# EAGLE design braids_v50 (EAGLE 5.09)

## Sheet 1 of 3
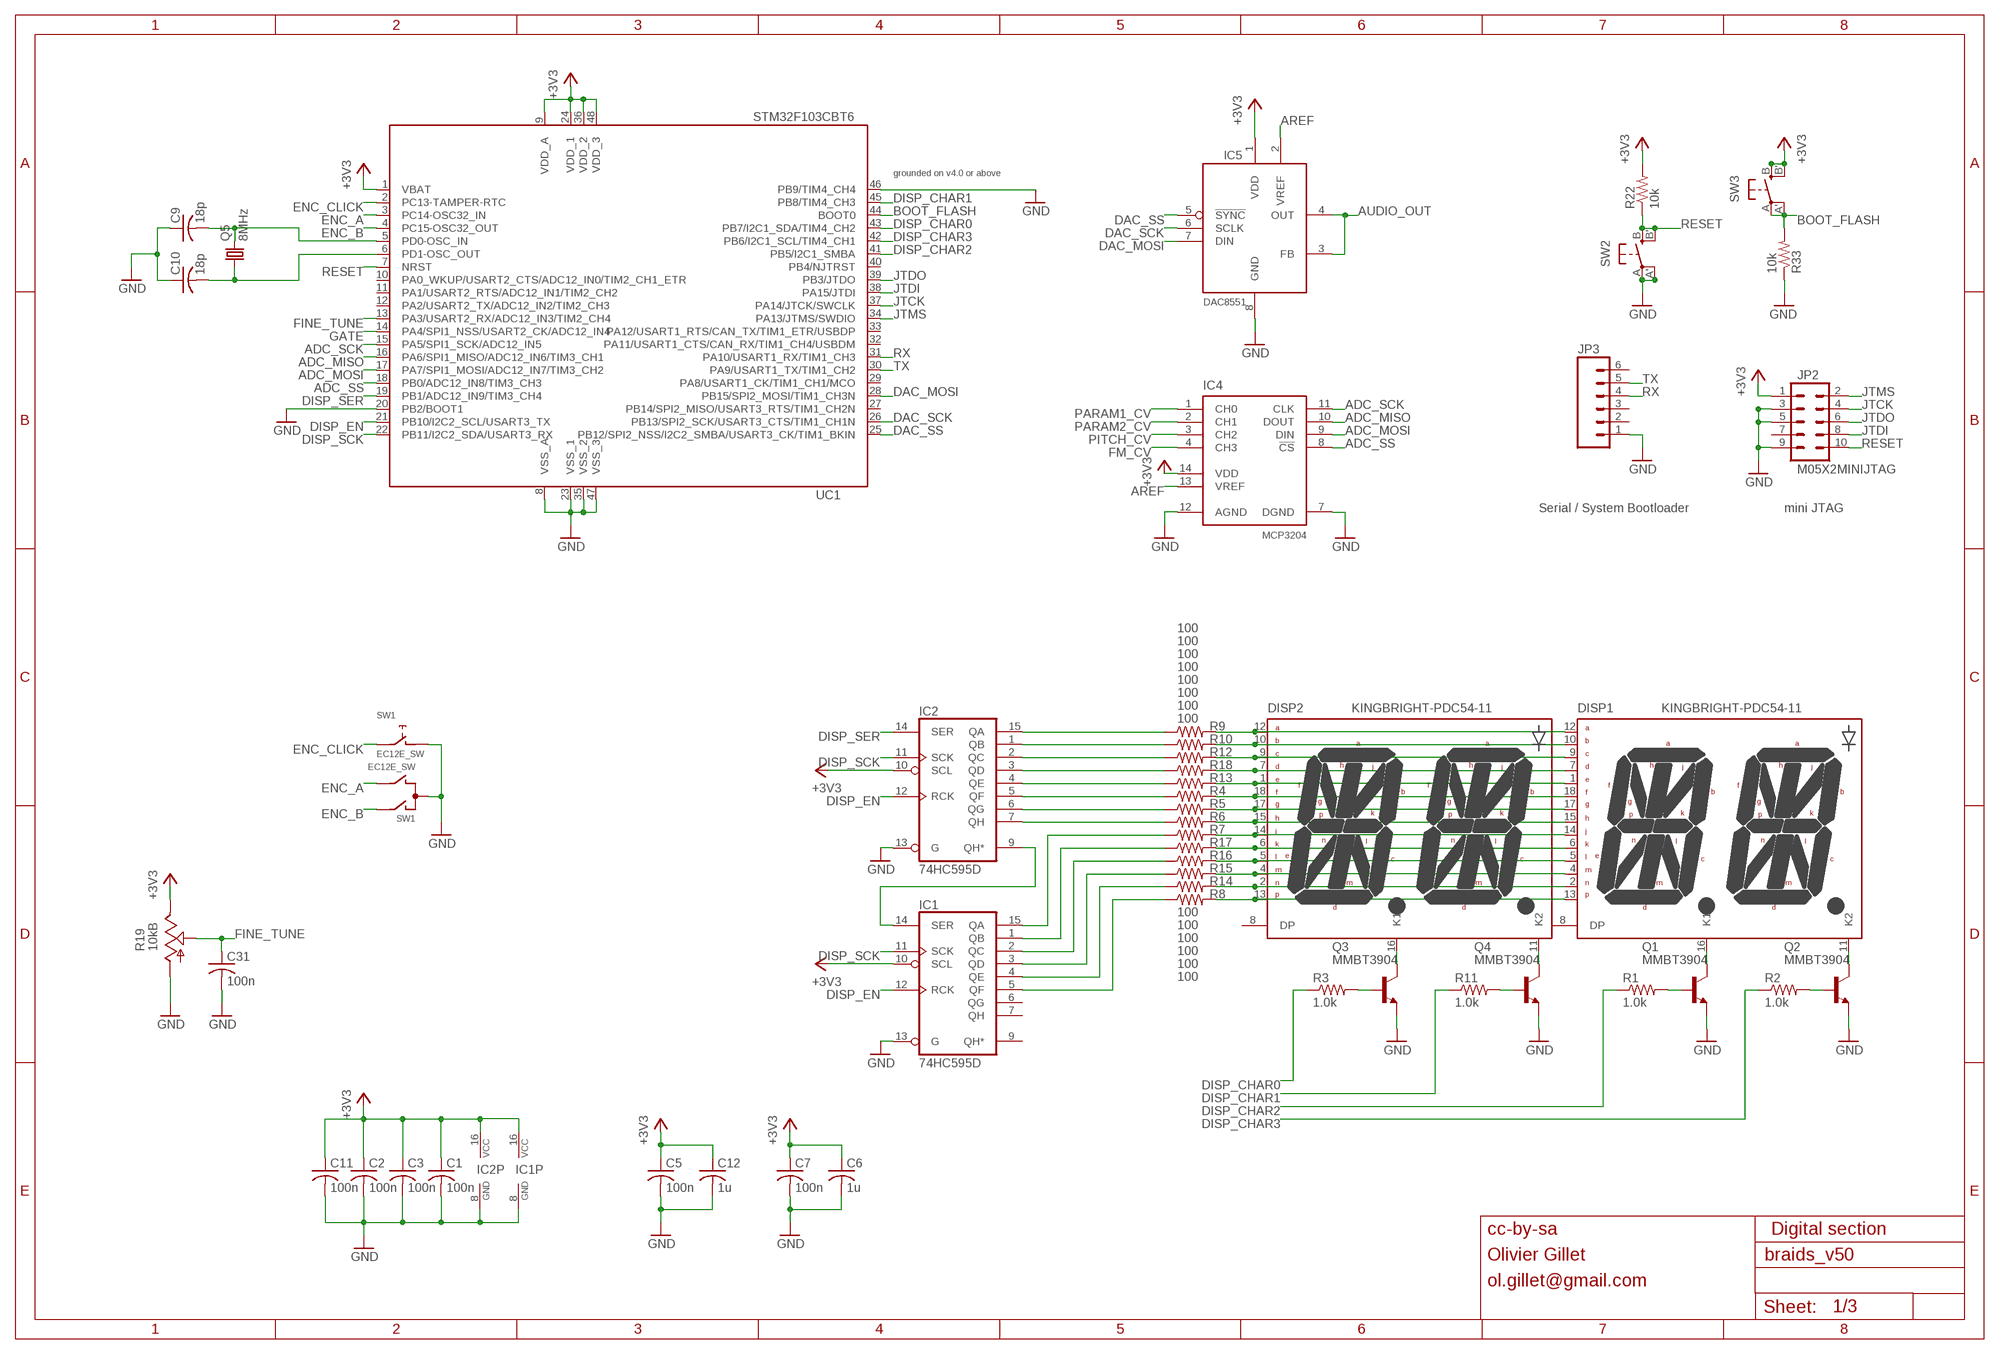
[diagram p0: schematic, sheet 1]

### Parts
C1  100n  C-USC0603  [C0603]
C2  100n  C-USC0603  [C0603]
C3  100n  C-USC0603  [C0603]
C5  100n  C-USC0603  [C0603]
C6  1u  C-USC0603  [C0603]
C7  100n  C-USC0603  [C0603]
C9  18p  C-USC0603  [C0603]
C10  18p  C-USC0603  [C0603]
C11  100n  C-USC0603  [C0603]
C12  1u  C-USC0603  [C0603]
C31  100n  C-USC0603  [C0603]
DISP1  KINGBRIGHT-PDC54-11  [PDC54]
DISP2  KINGBRIGHT-PDC54-11  [PDC54]
IC1  74HC595D  [SO16]
IC2  74HC595D  [SO16]
IC4  MCP3204  MCP3302  [SO14]
IC5  DAC8551  DAC855X  [MSOP-8]
JP2  M05X2MINIJTAG  [2X5-1.27]
JP3  M06SIP  [1X06]
Q1  MMBT3904  MMBT3904LT1-NPN-SOT23-BEC  [SOT23-BEC]
Q2  MMBT3904  MMBT3904LT1-NPN-SOT23-BEC  [SOT23-BEC]
Q3  MMBT3904  MMBT3904LT1-NPN-SOT23-BEC  [SOT23-BEC]
Q4  MMBT3904  MMBT3904LT1-NPN-SOT23-BEC  [SOT23-BEC]
Q5  8MHz  CRYSTALHC49UP  [HC49UP]
R1  1.0k  R-US_R0603  [R0603]
R2  1.0k  R-US_R0603  [R0603]
R3  1.0k  R-US_R0603  [R0603]
R4  100  R-US_R0603  [R0603]
R5  100  R-US_R0603  [R0603]
R6  100  R-US_R0603  [R0603]
R7  100  R-US_R0603  [R0603]
R8  100  R-US_R0603  [R0603]
R9  100  R-US_R0603  [R0603]
R10  100  R-US_R0603  [R0603]
R11  1.0k  R-US_R0603  [R0603]
R12  100  R-US_R0603  [R0603]
R13  100  R-US_R0603  [R0603]
R14  100  R-US_R0603  [R0603]
R15  100  R-US_R0603  [R0603]
R16  100  R-US_R0603  [R0603]
R17  100  R-US_R0603  [R0603]
R18  100  R-US_R0603  [R0603]
R19  10kB  POT_USVERTICAL_PS  [ALPS_POT_VERTICAL_PS]
R22  10k  R-US_R0603  [R0603]
R33  10k  R-US_R0603  [R0603]
SW1  EC12E_SW  [ALPS_EC12E_SW]
SW2  EVQQ2  [EVQ-Q2]
SW3  EVQQ2  [EVQ-Q2]
UC1  STM32F103CBT6  STM32F103CB  [LQFP48]

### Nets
+3V3: C1.1 C2.1 C3.1 C5.1 C6.1 C7.1 C11.1 C12.1 IC1.10(SCL) IC1.16(VCC) IC2.10(SCL) IC2.16(VCC) IC4.14(VDD) IC5.1(VDD) JP2.1 R19.P$1(E) R22.2 SW3.B'(S1) SW3.B(S) UC1.1(VBAT) UC1.9(VDD_A) UC1.24(VDD_1) UC1.36(VDD_2) UC1.48(VDD_3) ; also sheet 2,3
ADC_MISO: IC4.10(DOUT) UC1.16(PA6/SPI1_MISO/ADC12_IN6/TIM3_CH1)
ADC_MOSI: IC4.9(DIN) UC1.17(PA7/SPI1_MOSI/ADC12_IN7/TIM3_CH2)
ADC_SCK: IC4.11(CLK) UC1.15(PA5/SPI1_SCK/ADC12_IN5)
ADC_SS: IC4.8(!CS) UC1.18(PB0/ADC12_IN8/TIM3_CH3)
AREF: IC4.13(VREF) IC5.2(VREF) ; also sheet 3
AUDIO_OUT: IC5.3(FB) IC5.4(OUT) ; also sheet 2
BOOT_FLASH: R33.2 SW3.A'(P1) SW3.A(P) UC1.44(BOOT0)
DAC_MOSI: IC5.7(DIN) UC1.28(PB15/SPI2_MOSI/TIM1_CH3N)
DAC_SCK: IC5.6(SCLK) UC1.26(PB13/SPI2_SCK/USART3_CTS/TIM1_CH1N)
DAC_SS: IC5.5(!SYNC) UC1.25(PB12/SPI2_NSS/I2C2_SMBA/USART3_CK/TIM1_BKIN)
DISP_CHAR0: R3.1 UC1.43(PB7/I2C1_SDA/TIM4_CH2)
DISP_CHAR1: R11.1 UC1.45(PB8/TIM4_CH3)
DISP_CHAR2: R1.1 UC1.41(PB5/I2C1_SMBA)
DISP_CHAR3: R2.1 UC1.42(PB6/I2C1_SCL/TIM4_CH1)
DISP_EN: IC1.12(RCK) IC2.12(RCK) UC1.21(PB10/I2C2_SCL/USART3_TX)
DISP_SCK: IC1.11(SCK) IC2.11(SCK) UC1.22(PB11/I2C2_SDA/USART3_RX)
DISP_SER: IC2.14(SER) UC1.19(PB1/ADC12_IN9/TIM3_CH4)
ENC_A: SW1.B UC1.3(PC14-OSC32_IN)
ENC_B: SW1.A UC1.4(PC15-OSC32_OUT)
ENC_CLICK: SW1.E UC1.2(PC13-TAMPER-RTC)
FINE_TUNE: C31.1 R19.P$2(S) UC1.13(PA3/USART2_RX/ADC12_IN3/TIM2_CH4)
FM_CV: IC4.4(CH3) ; also sheet 2
GATE: UC1.14(PA4/SPI1_NSS/USART2_CK/ADC12_IN4) ; also sheet 2
GND: C1.2 C2.2 C3.2 C5.2 C6.2 C7.2 C9.1 C10.1 C11.2 C12.2 C31.2 IC1.8(GND) IC1.13(G) IC2.8(GND) IC2.13(G) IC4.7(DGND) IC4.12(AGND) IC5.8(GND) JP2.3 JP2.5 JP2.9 JP3.1 Q1.E Q2.E Q3.E Q4.E R19.P$3(A) R33.1 SW1.C SW1.D SW2.A'(P1) SW2.A(P) UC1.8(VSS_A) UC1.20(PB2/BOOT1) UC1.23(VSS_1) UC1.35(VSS_2) UC1.46(PB9/TIM4_CH4) UC1.47(VSS_3) ; also sheet 2,3
JTCK: JP2.4 UC1.37(PA14/JTCK/SWCLK)
JTDI: JP2.8 UC1.38(PA15/JTDI)
JTDO: JP2.6 UC1.39(PB3/JTDO)
JTMS: JP2.2 UC1.34(PA13/JTMS/SWDIO)
N$1: DISP2.16(K1) Q3.C
N$2: DISP2.11(K2) Q4.C
N$3: DISP1.16(K1) Q1.C
N$4: DISP1.11(K2) Q2.C
N$5: Q3.B R3.2
N$6: Q4.B R11.2
N$7: C9.2 Q5.2 UC1.5(PD0-OSC_IN)
N$8: C10.2 Q5.1 UC1.6(PD1-OSC_OUT)
N$9: Q1.B R1.2
N$10: Q2.B R2.2
N$15: DISP1.12(A) DISP2.12(A) R9.2
N$16: DISP1.10(B) DISP2.10(B) R10.2
N$17: DISP1.9(C) DISP2.9(C) R12.2
N$18: DISP1.7(D) DISP2.7(D) R18.2
N$19: DISP1.1(E) DISP2.1(E) R13.2
N$20: DISP1.18(F) DISP2.18(F) R4.2
N$21: DISP1.17(G) DISP2.17(G) R5.2
N$22: DISP1.15(H) DISP2.15(H) R6.2
N$23: DISP1.14(J) DISP2.14(J) R7.2
N$24: DISP1.6(K) DISP2.6(K) R17.2
N$25: DISP1.5(L) DISP2.5(L) R16.2
N$26: DISP1.4(M) DISP2.4(M) R15.2
N$27: DISP1.2(N) DISP2.2(N) R14.2
N$28: DISP1.13(P) DISP2.13(P) R8.2
N$30: IC2.7(QH) R6.1
N$31: IC1.14(SER) IC2.9(QH*)
N$32: IC2.15(QA) R9.1
N$33: IC2.1(QB) R10.1
N$34: IC2.2(QC) R12.1
N$35: IC2.3(QD) R18.1
N$36: IC2.4(QE) R13.1
N$37: IC2.5(QF) R4.1
N$38: IC2.6(QG) R5.1
N$39: IC1.15(QA) R7.1
N$40: IC1.1(QB) R17.1
N$41: IC1.2(QC) R16.1
N$42: IC1.3(QD) R15.1
N$43: IC1.4(QE) R14.1
N$44: IC1.5(QF) R8.1
PARAM1_CV: IC4.1(CH0) ; also sheet 2
PARAM2_CV: IC4.2(CH1) ; also sheet 2
PITCH_CV: IC4.3(CH2) ; also sheet 2
RESET: JP2.10 R22.1 SW2.B'(S1) SW2.B(S) UC1.7(NRST)
RX: JP3.4 UC1.31(PA10/USART1_RX/TIM1_CH3)
TX: JP3.5 UC1.30(PA9/USART1_TX/TIM1_CH2)
Unconnected: DISP1.8(DP) DISP2.8(DP) IC1.6(QG) IC1.7(QH) IC1.9(QH*) JP2.7 JP3.2 JP3.3 JP3.6 SW1.GND1(G) SW1.GND2(G) UC1.10(PA0_WKUP/USART2_CTS/ADC12_IN0/TIM2_CH1_ETR) UC1.11(PA1/USART2_RTS/ADC12_IN1/TIM2_CH2) UC1.12(PA2/USART2_TX/ADC12_IN2/TIM2_CH3) UC1.27(PB14/SPI2_MISO/USART3_RTS/TIM1_CH2N) UC1.29(PA8/USART1_CK/TIM1_CH1/MCO) UC1.32(PA11/USART1_CTS/CAN_RX/TIM1_CH4/USBDM) UC1.33(PA12/USART1_RTS/CAN_TX/TIM1_ETR/USBDP) UC1.40(PB4/NJTRST)

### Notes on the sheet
- grounded on v4.0 or above
- Serial / System Bootloader | mini JTAG
- cc-by-sa | Digital section
- Olivier Gillet
- ol.gillet@gmail.com

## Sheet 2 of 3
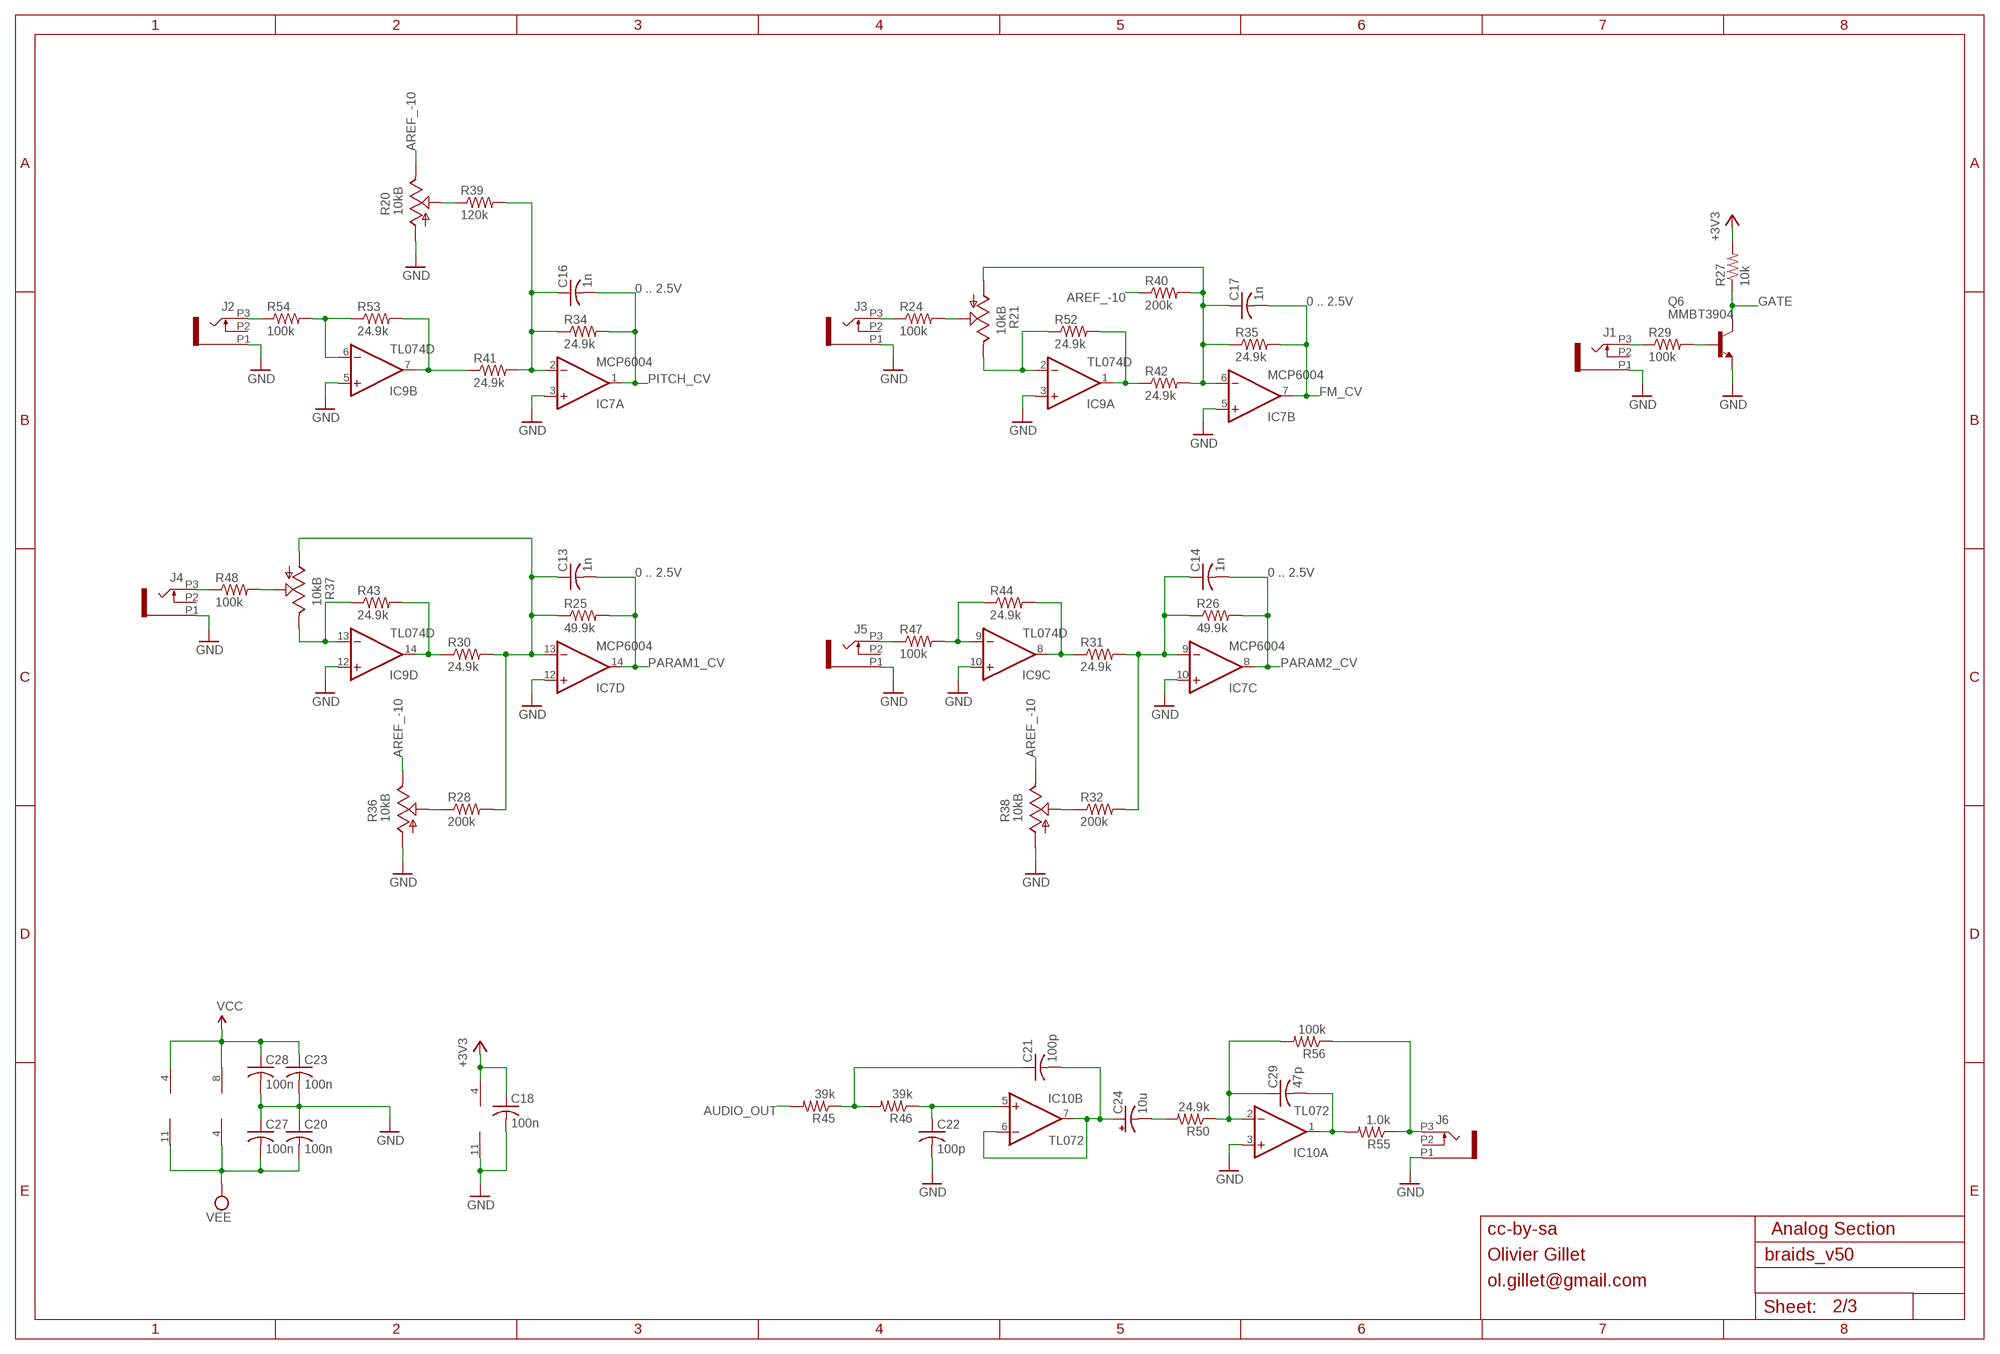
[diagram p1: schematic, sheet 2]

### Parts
C13  1n  C-USC0603  [C0603]
C14  1n  C-USC0603  [C0603]
C16  1n  C-USC0603  [C0603]
C17  1n  C-USC0603  [C0603]
C18  100n  C-USC0603  [C0603]
C20  100n  C-USC0603  [C0603]
C21  100p  C-USC0603  [C0603]
C22  100p  C-USC0603  [C0603]
C23  100n  C-USC0603  [C0603]
C24  10u  CPOL-USB  [PANASONIC_B]
C27  100n  C-USC0603  [C0603]
C28  100n  C-USC0603  [C0603]
C29  47p  C-USC0603  [C0603]
IC7  MCP6004  TL074D  [SO14]
IC9  TL074D  [SO14]
IC10  TL072  TL072D  [SO08]
J1  PJ301_THONKICONN6  [WQP_PJ_301M6]
J2  PJ301_THONKICONN6  [WQP_PJ_301M6]
J3  PJ301_THONKICONN6  [WQP_PJ_301M6]
J4  PJ301_THONKICONN6  [WQP_PJ_301M6]
J5  PJ301_THONKICONN6  [WQP_PJ_301M6]
J6  PJ301_THONKICONN6  [WQP_PJ_301M6]
Q6  MMBT3904  MMBT3904LT1-NPN-SOT23-BEC  [SOT23-BEC]
R20  10kB  POT_USVERTICAL_PS  [ALPS_POT_VERTICAL_PS]
R21  10kB  POT_USVERTICAL_PS  [ALPS_POT_VERTICAL_PS]
R24  100k  R-US_R0603  [R0603]
R25  49.9k  R-US_R0603  [R0603]
R26  49.9k  R-US_R0603  [R0603]
R27  10k  R-US_R0603  [R0603]
R28  200k  R-US_R0603  [R0603]
R29  100k  R-US_R0603  [R0603]
R30  24.9k  R-US_R0603  [R0603]
R31  24.9k  R-US_R0603  [R0603]
R32  200k  R-US_R0603  [R0603]
R34  24.9k  R-US_R0603  [R0603]
R35  24.9k  R-US_R0603  [R0603]
R36  10kB  POT_USVERTICAL_PS  [ALPS_POT_VERTICAL_PS]
R37  10kB  POT_USVERTICAL_PS  [ALPS_POT_VERTICAL_PS]
R38  10kB  POT_USVERTICAL_PS  [ALPS_POT_VERTICAL_PS]
R39  120k  R-US_R0603  [R0603]
R40  200k  R-US_R0603  [R0603]
R41  24.9k  R-US_R0603  [R0603]
R42  24.9k  R-US_R0603  [R0603]
R43  24.9k  R-US_R0603  [R0603]
R44  24.9k  R-US_R0603  [R0603]
R45  39k  R-US_R0603  [R0603]
R46  39k  R-US_R0603  [R0603]
R47  100k  R-US_R0603  [R0603]
R48  100k  R-US_R0603  [R0603]
R50  24.9k  R-US_R0603  [R0603]
R52  24.9k  R-US_R0603  [R0603]
R53  24.9k  R-US_R0603  [R0603]
R54  100k  R-US_R0603  [R0603]
R55  1.0k  R-US_R0603  [R0603]
R56  100k  R-US_R0603  [R0603]

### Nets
+3V3: C18.1 IC7.4(P:V+) R27.2 ; also sheet 1,3
AREF_-10: R20.P$1(E) R36.P$1(E) R38.P$1(E) R40.1 ; also sheet 3
AUDIO_OUT: R45.2 ; also sheet 1
FM_CV: C17.2 IC7.7(B:OUT) R35.2 ; also sheet 1
GATE: Q6.C R27.1 ; also sheet 1
GND: C18.2 C20.1 C22.2 C23.2 C27.1 C28.2 IC7.3(A:+IN) IC7.5(B:+IN) IC7.10(C:+IN) IC7.11(P:V-) IC7.12(D:+IN) IC9.3(A:+IN) IC9.5(B:+IN) IC9.10(C:+IN) IC9.12(D:+IN) IC10.3(A:+IN) J1.P1 J2.P1 J3.P1 J4.P1 J5.P1 J6.P1 Q6.E R20.P$3(A) R36.P$3(A) R38.P$3(A) ; also sheet 1,3
N$12: IC9.7(B:OUT) R41.1 R53.2
N$13: R20.P$2(S) R39.1
N$14: J2.P3 R54.1
N$29: C16.1 IC7.2(A:-IN) R34.1 R39.2 R41.2
N$45: IC9.6(B:-IN) R53.1 R54.2
N$46: J3.P3 R24.1
N$47: J4.P3 R48.1
N$48: R21.P$2(S) R24.2
N$50: IC9.13(D:-IN) R37.P$1(E) R43.1
N$51: IC9.14(D:OUT) R30.1 R43.2
N$52: IC9.2(A:-IN) R21.P$1(E) R52.1
N$53: IC9.1(A:OUT) R42.1 R52.2
N$55: C17.1 IC7.6(B:-IN) R21.P$3(A) R35.1 R40.2 R42.2
N$57: J1.P3 R29.1
N$58: IC9.8(C:OUT) R31.1 R44.2
N$59: C13.1 IC7.13(D:-IN) R25.1 R28.2 R30.2 R37.P$3(A)
N$60: J5.P3 R47.1
N$61: R28.1 R36.P$2(S)
N$62: R37.P$2(S) R48.2
N$63: IC9.9(C:-IN) R44.1 R47.2
N$65: R32.1 R38.P$2(S)
N$66: Q6.B R29.2
N$67: C21.2 C24.+ IC10.6(B:-IN) IC10.7(B:OUT)
N$68: C24.- R50.2
N$69: C22.1 IC10.5(B:+IN) R46.1
N$70: C14.1 IC7.9(C:-IN) R26.1 R31.2 R32.2
N$71: C21.1 R45.1 R46.2
N$72: J6.P3 R55.1 R56.1
N$73: C29.2 IC10.1(A:OUT) R55.2
N$75: C29.1 IC10.2(A:-IN) R50.1 R56.2
PARAM1_CV: C13.2 IC7.14(D:OUT) R25.2 ; also sheet 1
PARAM2_CV: C14.2 IC7.8(C:OUT) R26.2 ; also sheet 1
PITCH_CV: C16.2 IC7.1(A:OUT) R34.2 ; also sheet 1
VCC: C23.1 C28.1 IC9.4(P:V+) IC10.8(P:V+) ; also sheet 3
VEE: C20.2 C27.2 IC9.11(P:V-) IC10.4(P:V-) ; also sheet 3
Unconnected: J1.P2 J2.P2 J3.P2 J4.P2 J5.P2 J6.P2

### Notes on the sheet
- 0 .. 2.5V
- 0 .. 2.5V
- 0 .. 2.5V | 0 .. 2.5V
- cc-by-sa | Analog Section
- Olivier Gillet
- ol.gillet@gmail.com

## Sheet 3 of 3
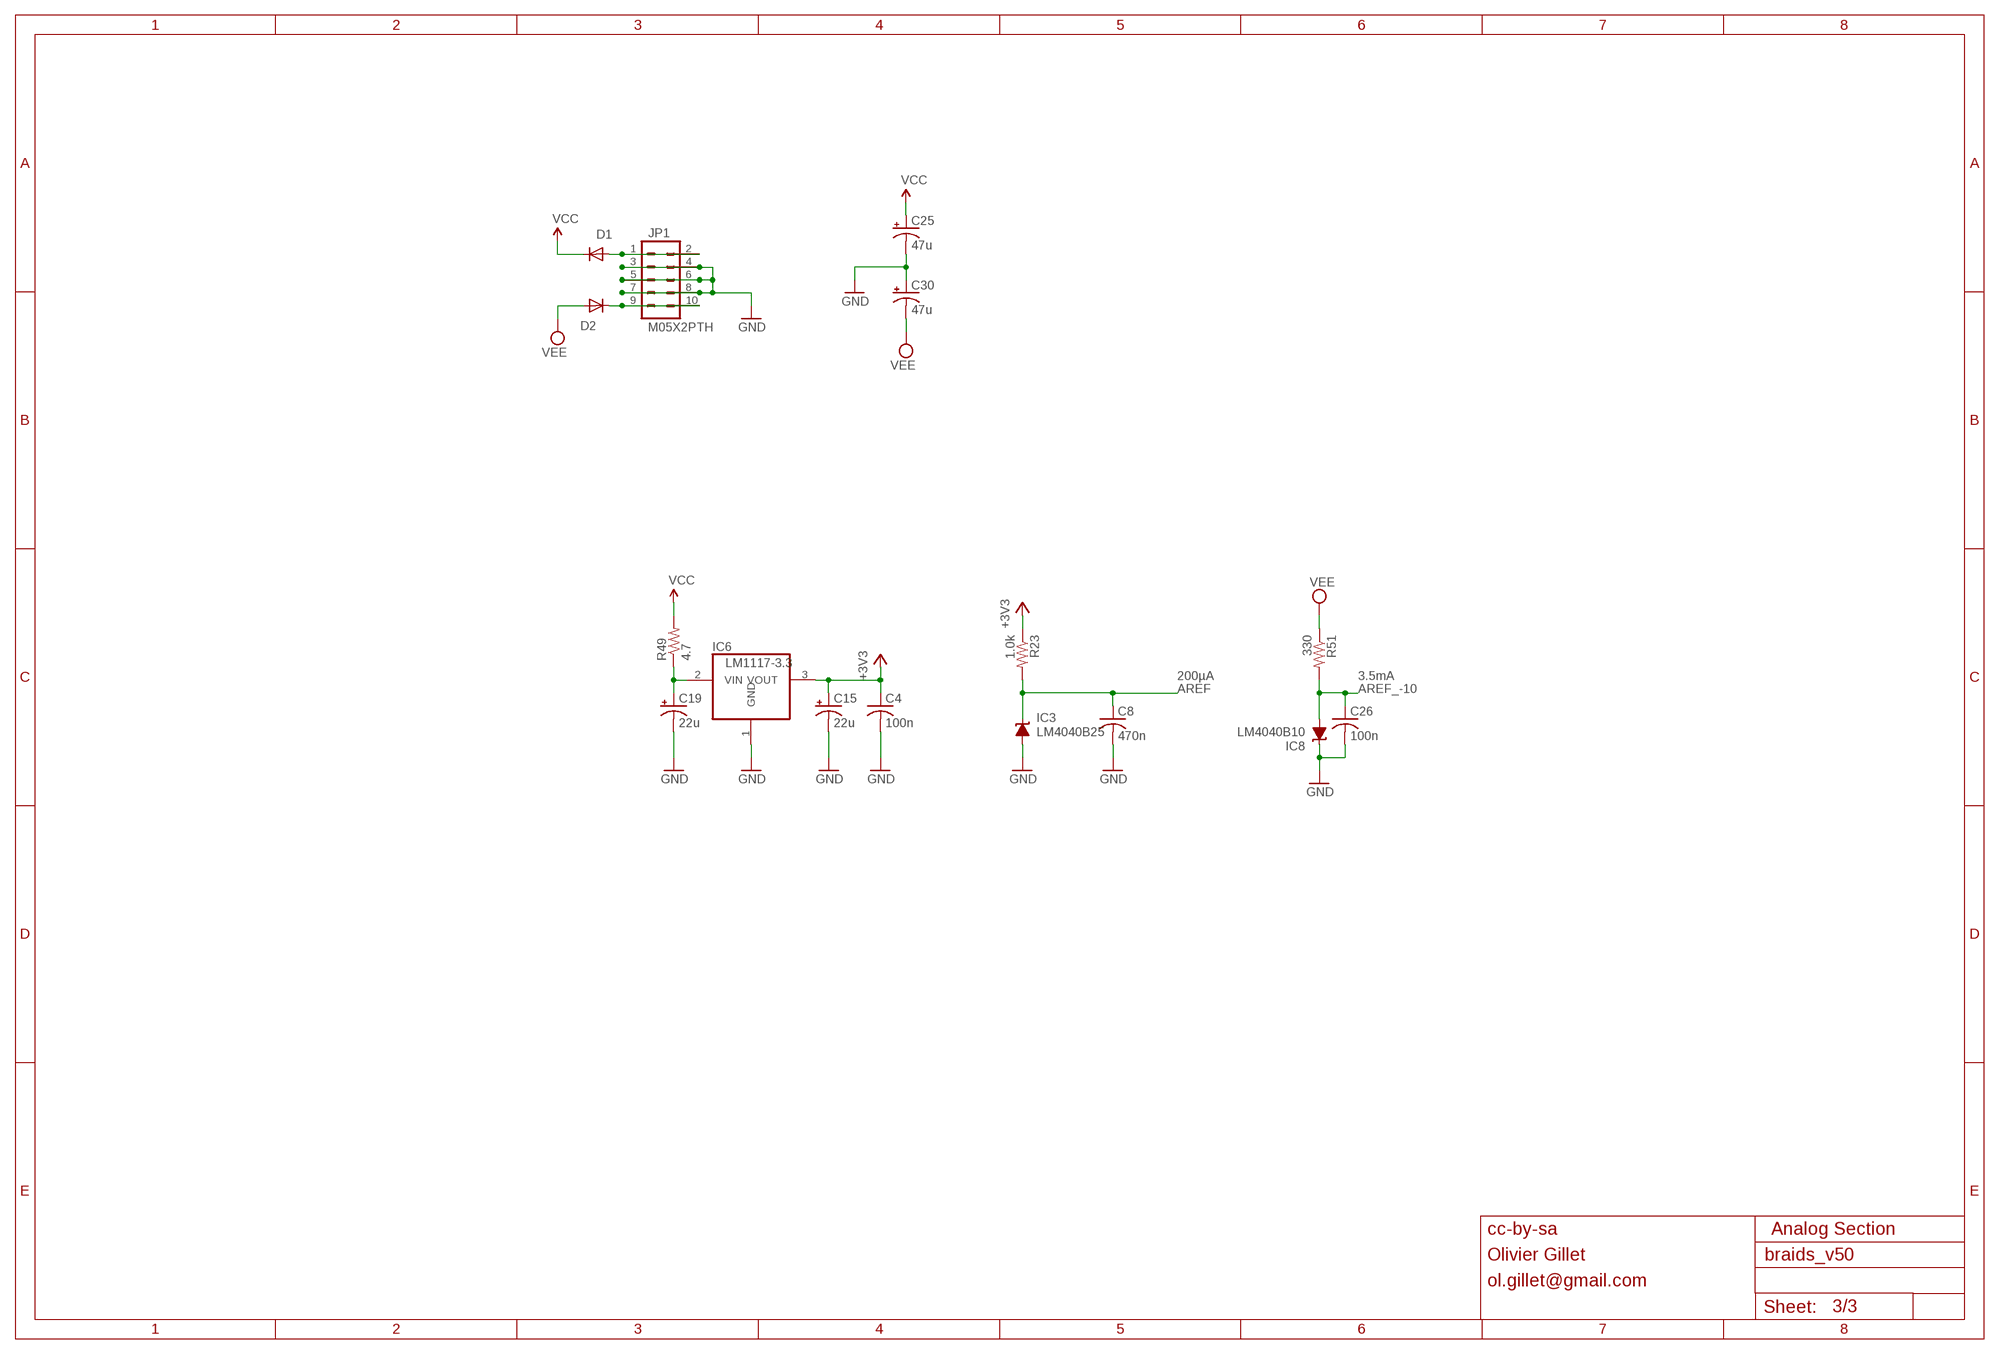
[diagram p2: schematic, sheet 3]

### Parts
C4  100n  C-USC0603  [C0603]
C8  470n  C-USC0603  [C0603]
C15  22u  CPOL-USC  [PANASONIC_C]
C19  22u  CPOL-USC  [PANASONIC_C]
C25  47u  CPOL-USD  [PANASONIC_D]
C26  100n  C-USC0603  [C0603]
C30  47u  CPOL-USD  [PANASONIC_D]
D1  1N5819HW  DIODE-SOD123  [SOD123]
D2  1N5819HW  DIODE-SOD123  [SOD123]
IC3  LM4040B25  LM4041B12DBZ  [DBZ_R-PDSO-G3]
IC6  LM1117-3.3  REG1117T  [TO252]
IC8  LM4040B10  LM4041B12DBZ  [DBZ_R-PDSO-G3]
JP1  M05X2PTH  [AVR_ICSP]
R23  1.0k  R-US_R0603  [R0603]
R49  4.7  R-US_R1206  [R1206]
R51  330  R-US_R0603  [R0603]

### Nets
+3V3: C4.1 C15.+ IC6.3(VOUT) R23.1 ; also sheet 1,2
AREF: C8.1 IC3.1(C) R23.2 ; also sheet 1
AREF_-10: C26.1 IC8.2(A) R51.2 ; also sheet 2
GND: C4.2 C8.2 C15.- C19.- C25.- C26.2 C30.+ IC3.2(A) IC6.1(GND) IC8.1(C) JP1.3 JP1.4 JP1.5 JP1.6 JP1.7 JP1.8 ; also sheet 1,2
N$49: C19.+ IC6.2(VIN) R49.1
N$56: D1.A JP1.1 JP1.2
N$64: D2.C JP1.9 JP1.10
VCC: C25.+ D1.C R49.2 ; also sheet 2
VEE: C30.- D2.A R51.1 ; also sheet 2

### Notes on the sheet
- 200µA | 3.5mA
- cc-by-sa | Analog Section
- Olivier Gillet
- ol.gillet@gmail.com

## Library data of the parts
C1-C14 C16-C18 C20-C23 C26-C29 C31 = rcl:C-US: CAPACITOR, American symbol
C15 C19 C24 C25 C30 = rcl:CPOL-US: POLARIZED CAPACITOR, American symbol
D1 D2 = diode:DIODE-: DIODE
DISP1 DISP2 = og-display:KINGBRIGHT-PDC54-11: Kingbright PDC54-11GWA ; also compatible with LITE-On LTP-3784G or Avago HDSP-A27C
IC1 IC2 = 74xx-eu:74*595: 8-bit SHIFT REGISTER, output latch
IC3 IC8 = texas:LM4041: PRECISION MICROPOWER SHUNT VOLTAGE REFERENCE
IC4 = og-adc:MCP3302
IC5 = og-dac:DAC855X: 16-bit low-glitch DAC with 2's complement (8550) or unsigned code (8551)
IC6 = og-vreg:REG1117: 800mA and 1A Low Dropout (LDO) Positive Regulator 1.8V, 2.5V, 2.85V, 3.3V, 5V, and Adj
IC7 IC9 = gm-ics:TL074: OP AMP
IC10 = linear:TL072: OP AMP
J1-J6 = og-pj301:PJ301_THONKICONN
JP1 JP2 = og-header:M05X2: Header 5x2 Standard 10-pin dual row 0.1" header. Commonly used with AVR-ISP. Use with Spark Fun Electronics SKU: PRT-00778
JP3 = SparkFun:M06: Header 6 Standard 6-pin 0.1" header. Use with straight break away headers (SKU : PRT-00116), right angle break away headers (PRT-00553), swiss pins (PRT-00743), machine pins (PRT-00117), and female headers (PRT-00115). Molex polarized connector foot print use with SKU : PRT-08094 with associated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
Q1-Q4 Q6 = transistor:*-NPN-: NPN Transistror BF959 corrected 2008.03.06
Q5 = crystal:CRYSTAL: CRYSTAL
R1-R18 R22-R35 R39-R56 = rcl:R-US_: RESISTOR, American symbol
R19-R21 R36-R38 = pot-alps:POT_US
SW1 = og-encoder:EC12E_SW: ALPS rotary Encoder EC12E series with switch
SW2 SW3 = adafruit:EVQQ2: SMT 6mm switch, EVQQ2 series http://www.ladyada.net/library/eagle
UC1 = stm32:STM32F103CB

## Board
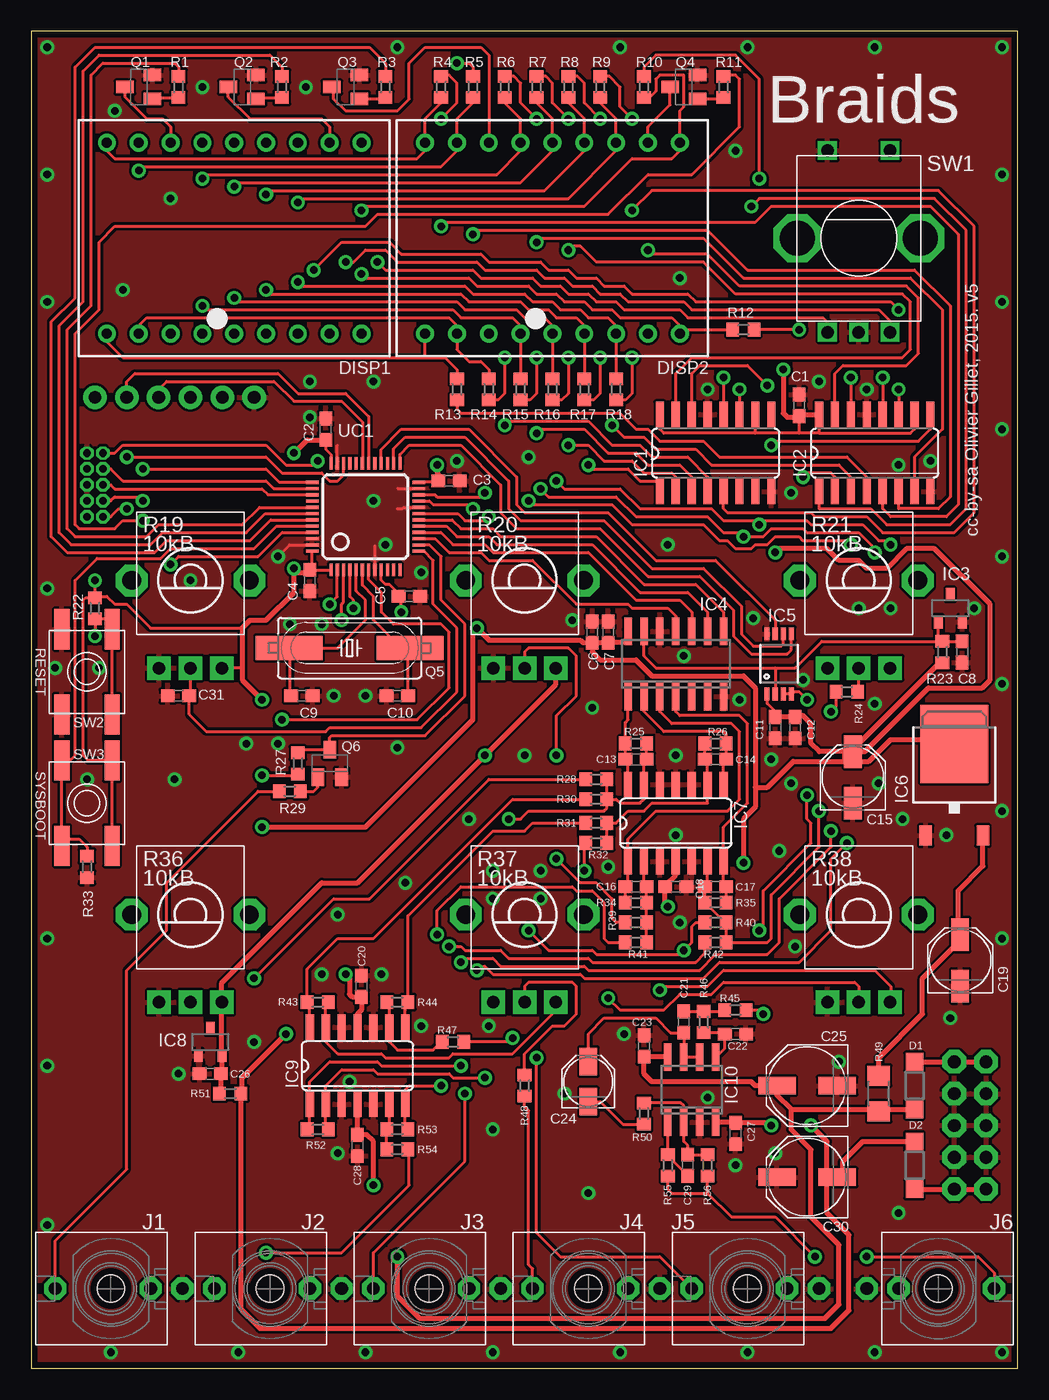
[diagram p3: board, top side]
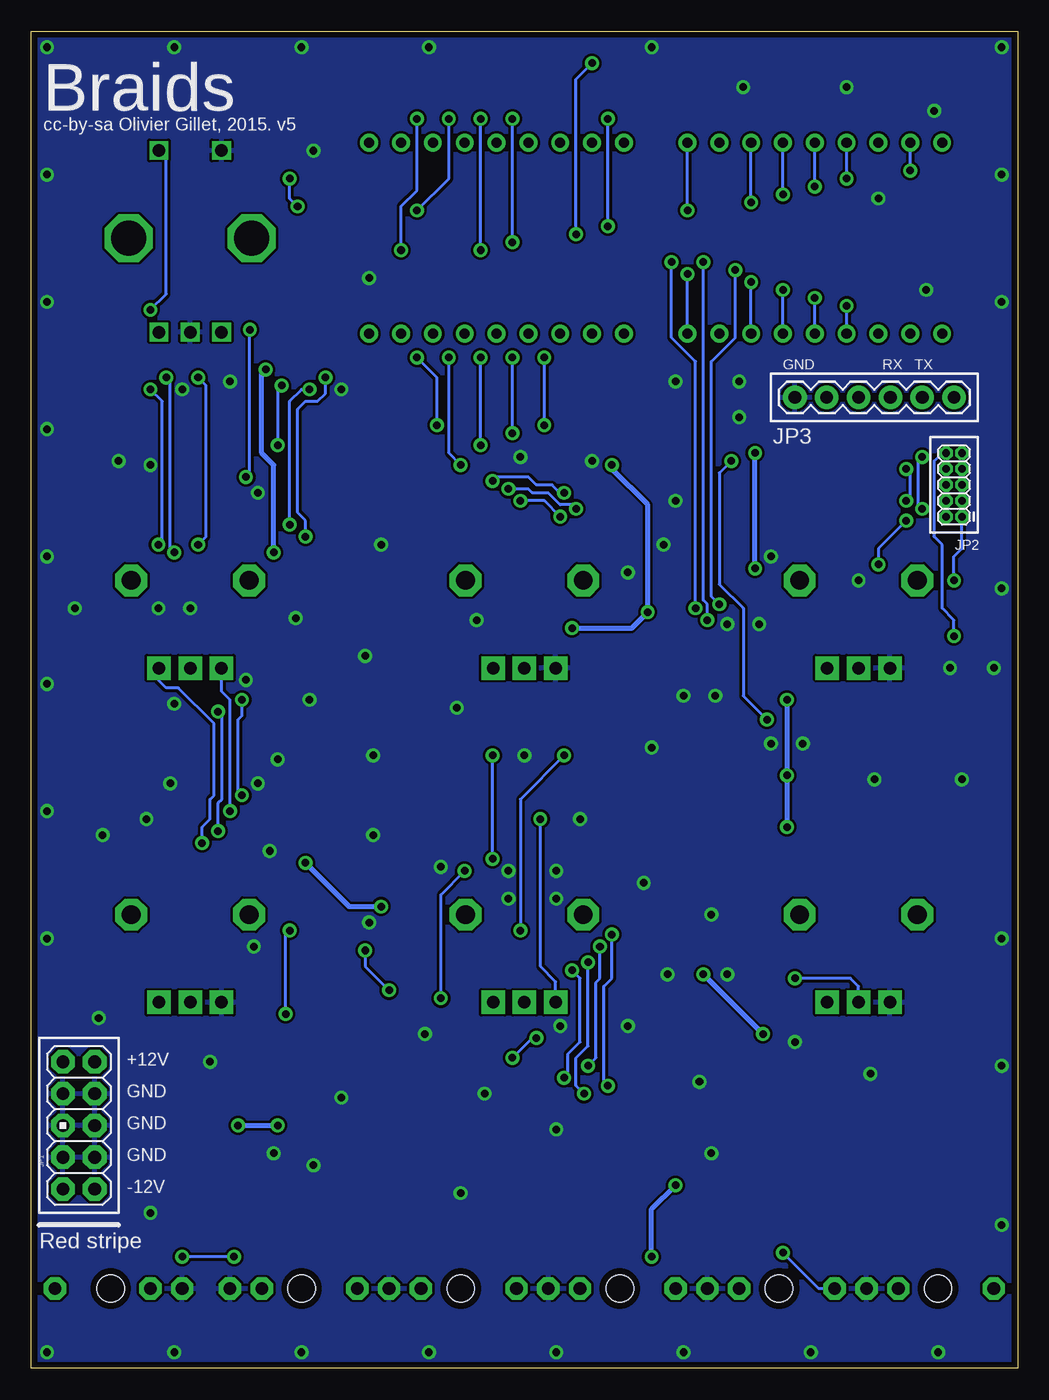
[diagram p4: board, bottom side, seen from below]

Size 78.72 x 106.68 mm. Coordinates in mm from the lower left corner, seen from the top.
Outline: 0,0 78.72,0 78.72,106.68 0,106.68 0,0
Copper layers (1*16): Top 0.035mm / dielectric 1.5mm / Bottom 0.035mm
Design rules "PCBCart-Standard *": minimum track width 8mil, minimum drill 0.4mm, track to track 8mil, track to pad 8mil, pad to pad 8mil, via to via 8mil, smd to smd 8mil, copper to edge 20mil, drill to drill 8mil, minimum pad ring 8mil, minimum via ring 10mil, stop-mask expansion 3mil, vias tented up to drill 25mil, thermal gap 8mil

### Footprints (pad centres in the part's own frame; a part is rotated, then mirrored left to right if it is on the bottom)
C0603 = smd 1.1 x 1: 1 -0.85,0; 2 0.85,0
PANASONIC_C = smd 2.6 x 1.4: + 2.05,0; - -2.05,0
PANASONIC_B = smd 2.2 x 1.4: + 1.6,0; - -1.6,0
PANASONIC_D = smd 3 x 1.4: + 2.4,0; - -2.4,0
SOD123 = smd 1.4 x 1.4: A 1.9,0; C -1.9,0
PDC54 = drill 0.8 pad 1.422 round: 1 -10.16,-7.62; 2 -7.62,-7.62; 3 -5.08,-7.62; 4 -2.54,-7.62; 5 0,-7.62; 6 2.54,-7.62; 7 5.08,-7.62; 8 7.62,-7.62; 9 10.16,-7.62; 10 10.16,7.62; 11 7.62,7.62; 12 5.08,7.62; 13 2.54,7.62; 14 0,7.62; 15 -2.54,7.62; 16 -5.08,7.62; 17 -7.62,7.62; 18 -10.16,7.62
SO16 = smd 0.66 x 2.032: 1 -4.445,-3.073; 2 -3.175,-3.073; 3 -1.905,-3.073; 4 -0.635,-3.073; 5 0.635,-3.073; 6 1.905,-3.073; 7 3.175,-3.073; 8 4.445,-3.073; 9 4.445,3.073; 10 3.175,3.073; 11 1.905,3.073; 12 0.635,3.073; 13 -0.635,3.073; 14 -1.905,3.073; 15 -3.175,3.073; 16 -4.445,3.073
DBZ_R-PDSO-G3 = smd 0.7 x 1: 1 -0.95,-1.1; 2 0.95,-1.1; 3 0,1.1
SO14 = smd 0.6 x 2.2: 1 -3.81,-2.6; 2 -2.54,-2.6; 3 -1.27,-2.6; 4 0,-2.6; 5 1.27,-2.6; 6 2.54,-2.6; 7 3.81,-2.6; 8 3.81,2.6; 9 2.54,2.6; 10 1.27,2.6; 11 0,2.6; 12 -1.27,2.6; 13 -2.54,2.6; 14 -3.81,2.6
MSOP-8 = smd 0.41 x 1.02: 1 -0.975,-2.4; 2 -0.325,-2.4; 3 0.325,-2.4; 4 0.975,-2.4; 5 0.975,2.4; 6 0.325,2.4; 7 -0.325,2.4; 8 -0.975,2.4
TO252 = smd 1 x 1.6: 1 -2.28,-4.8; 2 2.28,-4.8 | smd 5.4 x 6.2: 3 0,2.5
SO14' = smd 0.66 x 2.032: 1 -3.81,-3.073; 2 -2.54,-3.073; 3 -1.27,-3.073; 4 0,-3.073; 5 1.27,-3.073; 6 2.54,-3.073; 7 3.81,-3.073; 8 3.81,3.073; 9 2.54,3.073; 10 1.27,3.073; 11 0,3.073; 12 -1.27,3.073; 13 -2.54,3.073; 14 -3.81,3.073
SO08 = smd 0.6 x 2.2: 1 -1.905,-2.6; 2 -0.635,-2.6; 3 0.635,-2.6; 4 1.905,-2.6; 5 1.905,2.6; 6 0.635,2.6; 7 -0.635,2.6; 8 -1.905,2.6
WQP_PJ_301M6 = drill 1.016 pad 1.778 octagon: P1 0,-5.715; P2 0,-3.175; P3 0,4.445 | hole 2.2: 0,0
AVR_ICSP = drill 1.016 pad 1.88 octagon: 1 -1.27,5.08; 2 1.27,5.08; 3 -1.27,2.54; 4 1.27,2.54; 5 -1.27,0; 6 1.27,0; 7 -1.27,-2.54; 8 1.27,-2.54; 9 -1.27,-5.08; 10 1.27,-5.08
2X5-1.27 = drill 0.61 pad 1.067 octagon: 1 -1.27,3.81; 2 0,3.81; 3 -1.27,2.54; 4 0,2.54; 5 -1.27,1.27; 6 0,1.27; 7 -1.27,0; 8 0,0; 9 -1.27,-1.27; 10 0,-1.27
1X06 = drill 1.016 pad 1.88 round: 1 0,0; 2 2.54,0; 3 5.08,0; 4 7.62,0; 5 10.16,0; 6 12.7,0
SOT23-BEC = smd 1 x 1.4: B -0.95,-1.1; C 0,1.1; E 0.95,-1.1
HC49UP = smd 5.334 x 1.93: 1 -4.826,0; 2 4.826,0
R0603 = smd 1 x 1.1: 1 -0.85,0; 2 0.85,0
ALPS_POT_VERTICAL_PS = drill 1 pad 1.88 square: P$1 -2.5,7; P$2 0,7; P$3 2.5,7 | drill 1.5 pad 2.54 octagon: P$4 -4.7,0; P$5 4.7,0
R1206 = smd 1.6 x 1.803: 1 -1.422,0; 2 1.422,0
ALPS_EC12E_SW = drill 1 square: A -2.5,-7.5; B 2.5,-7.5; C 0,-7.5; D -2.5,7; E 2.5,7 | drill 2.8 octagon: GND1 -4.9,0; GND2 4.9,0
EVQ-Q2 = smd 3.2 x 1.2: A -3.4,-2; A' 3.4,-2; B -3.4,2; B' 3.4,2
LQFP48 = smd 0.254 x 1: 1 -2.75,-4.25; 2 -2.25,-4.25; 3 -1.75,-4.25; 4 -1.25,-4.25; 5 -0.75,-4.25; 6 -0.25,-4.25; 7 0.25,-4.25; 8 0.75,-4.25; 9 1.25,-4.25; 10 1.75,-4.25; 11 2.25,-4.25; 12 2.75,-4.25; 25 2.75,4.25; 26 2.25,4.25; 27 1.75,4.25; 28 1.25,4.25; 29 0.75,4.25; 30 0.25,4.25; 31 -0.25,4.25; 32 -0.75,4.25; 33 -1.25,4.25; 34 -1.75,4.25; 35 -2.25,4.25; 36 -2.75,4.25 | smd 1 x 0.254: 13 4.25,-2.75; 14 4.25,-2.25; 15 4.25,-1.75; 16 4.25,-1.25; 17 4.25,-0.75; 18 4.25,-0.25; 19 4.25,0.25; 20 4.25,0.75; 21 4.25,1.25; 22 4.25,1.75; 23 4.25,2.25; 24 4.25,2.75; 37 -4.25,2.75; 38 -4.25,2.25; 39 -4.25,1.75; 40 -4.25,1.25; 41 -4.25,0.75; 42 -4.25,0.25; 43 -4.25,-0.25; 44 -4.25,-0.75; 45 -4.25,-1.25; 46 -4.25,-1.75; 47 -4.25,-2.25; 48 -4.25,-2.75

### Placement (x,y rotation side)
C1  61.28,76.83 90 top
C2  23.5,74.93 90 top
C3  33.34,70.8 0 top
C4  22.23,62.87 270 top
C5  30.16,61.59 0 top
C6  44.77,58.74 90 top
C7  46.04,58.74 90 top
C8  74.3,57.15 270 top
C9  21.59,53.66 180 top
C10  29.21,53.66 0 top
C11  59.37,51.12 270 top
C12  60.96,51.12 270 top
C13  48.26,48.58 180 top
C14  54.61,48.58 0 top
C15  65.56,47.15 90 top
C16  48.26,38.42 180 top
C17  54.61,38.42 0 top
C18  51.44,38.42 0 top
C19  74.14,32.54 90 top
C20  26.35,30.48 270 top
C21  52.07,27.62 270 top
C22  56.2,26.67 0 top
C23  48.9,25.72 90 top
C24  44.45,22.86 90 top
C25  61.91,22.54 180 top
C26  14.29,23.5 180 top
C27  56.2,18.73 90 top
C28  26.04,17.78 270 top
C29  52.39,16.19 270 top
C30  61.91,15.24 180 top
C31  11.75,53.66 180 top
D1  70.48,22.54 90 top
D2  70.48,16.19 90 top
DISP1  16.19,90.17 0 top
DISP2  41.59,90.17 0 top
IC1  54.61,73.03 0 top
IC2  67.31,73.03 0 top
IC3  73.34,60.64 0 top
IC4  51.44,56.2 0 top
IC5  59.69,56.2 0 top
IC6  73.66,47.31 0 top
IC7  MCP6004  [SO14']  51.44,43.5 0 top
IC8  14.29,26.04 0 top
IC9  TL074D  [SO14']  26.04,24.13 0 top
IC10  52.7,22.23 0 top
J1  6.35,6.35 90 top
J2  19.05,6.35 90 top
J3  31.75,6.35 90 top
J4  44.45,6.35 90 top
J5  57.15,6.35 90 top
J6  72.39,6.35 270 top
JP1  74.93,19.37 0 bottom
JP2  5.71,71.75 180 bottom
JP3  17.78,77.47 0 bottom
Q1  8.57,102.23 90 top
Q2  16.83,102.23 90 top
Q3  25.08,102.23 90 top
Q4  52.07,102.23 90 top
Q5  25.4,57.47 180 top
Q6  23.81,48.26 0 top
R1  11.75,102.23 270 top
R2  20,102.23 270 top
R3  28.26,102.23 270 top
R4  32.7,102.23 270 top
R5  35.24,102.23 270 top
R6  37.78,102.23 270 top
R7  40.32,102.23 270 top
R8  42.86,102.23 270 top
R9  45.4,102.23 270 top
R10  48.9,102.23 270 top
R11  55.24,102.23 270 top
R12  56.83,82.87 180 top
R13  33.97,78.11 90 top
R14  36.51,78.11 90 top
R15  39.05,78.11 90 top
R16  41.59,78.11 90 top
R17  44.13,78.11 90 top
R18  46.67,78.11 90 top
R19  12.7,62.87 180 top
R20  39.37,62.87 180 top
R21  66.04,62.87 180 top
R22  5.08,60.64 90 top
R23  72.71,57.15 90 top
R24  65.09,53.98 0 top
R25  48.26,49.85 180 top
R26  54.61,49.85 0 top
R27  21.27,48.26 270 top
R28  45.09,46.99 0 top
R29  20.64,46.04 0 top
R30  45.09,45.4 0 top
R31  45.09,43.5 0 top
R32  45.09,41.91 0 top
R33  4.45,40.01 90 top
R34  48.26,37.15 180 top
R35  54.61,37.15 0 top
R36  12.7,36.2 180 top
R37  39.37,36.2 180 top
R38  66.04,36.2 180 top
R39  48.26,35.56 0 top
R40  54.61,35.56 0 top
R41  48.26,33.97 0 top
R42  54.61,33.97 0 top
R43  22.86,29.21 180 top
R44  29.21,29.21 0 top
R45  56.2,28.57 0 top
R46  53.66,27.62 90 top
R47  33.66,26.04 180 top
R48  39.37,22.54 90 top
R49  67.63,21.91 270 top
R50  48.9,20.32 270 top
R51  15.88,21.91 180 top
R52  22.86,19.05 180 top
R53  29.21,19.05 0 top
R54  29.21,17.46 180 top
R55  50.8,16.19 90 top
R56  53.98,16.19 90 top
SW1  66.04,90.17 0 top
SW2  4.45,55.56 270 top
SW3  4.45,45.09 270 top
UC1  26.67,67.94 0 top

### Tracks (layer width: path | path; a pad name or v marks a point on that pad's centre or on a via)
+3V3  (via drill 0.6)
  Top 0.254: IC1.16 50.16,74.93 50.48,74.61 57.78,74.61 | 62.87,74.61 70.17,74.61 70.48,74.93 IC2.10 | IC2.16 62.87,74.61 | 62.87,74.61 61.28,74.61 | 61.28,74.61 61.28,75.88 | 61.28,74.61 57.78,74.61 | 57.78,74.61 IC1.10 | C2.1 23.5,73.34 23.92,72.92 UC1.36 | R27.2 21.17,47.31 v18.41,47.31 | IC4.14 47.47,58.95 | 32.38,70.91 32.17,70.69 UC1.24 | UC1.48 22.42,63.91 C4.1 22.25,63.7 UC1.1 | UC1.9 27.92,62.88 28.26,62.55 28.57,62.55 29.21,61.91 29.21,61.7 C5.1 29.53,61.38 v29.53,60.33 | IC5.1 58.74,53.77 58.74,53.02 59.37,52.39 C11.1 | SW3.B' SW3.B 4.54,48.48 4.13,48.9 4.13,61.28 4.34,61.49 R22.2 5.18,61.59 | 5.18,61.59 6.03,61.59 6.67,60.96 7.62,60.96 9.53,59.05 16.83,59.05 | 5.18,61.59 5.08,61.7 v5.08,62.87 | R19.P$1 15.21,55.88 16.83,55.88
  Top 0.406: v60.01,79.69 60.01,76.2 60.33,75.88 61.17,75.88 C1.1 61.39,76.1 IC2.16 | v59.37,65.09 59.69,65.41 63.5,65.41 64.45,64.45 66.04,64.45 66.67,63.82 68.26,63.82 69.85,65.41 72.07,65.41 76.52,60.96 76.52,54.93 75.88,54.29 71.6,54.29 66.5,49.2 C15.+ | 32.38,70.91 C3.1 32.49,71.33 32.38,71.44 v32.38,72.07 | C4.1 22.01,63.5 20.95,63.5 v20.95,63.82 20.95,61.91 18.73,59.69 17.46,59.69 16.83,59.05 16.83,55.88 16.83,54.93 v18.41,53.34 | C6.1 44.03,57.89 43.81,58.1 36.51,58.1 v35.56,59.05 35.24,58.74 35.24,51.75 26.67,43.18 v18.41,43.18 | C6.1 44.77,57.15 45.4,56.52 48.26,56.52 49.53,55.24 56.83,55.24 57.78,54.29 57.78,46.35 | v56.83,40.32 56.83,43.81 57.78,44.77 57.78,46.35 | 57.78,46.35 58.74,46.35 60.8,48.42 64.93,48.42 | C11.1 C12.1 61.06,52.07 61.59,52.07 62.23,51.44 62.23,49.85 62.88,49.2 64.93,49.2 | v20.95,73.03 22.01,74.08 C2.1 | 64.93,49.2 C15.+ | 64.93,48.42 64.93,49.2 | 64.93,48.42 66.83,48.42 68.58,50.16 73.18,50.16 73.54,49.81 IC6.3 | 65.56,49.85 66.04,49.85 | 65.56,49.85 | C15.+ 65.56,49.85 | C6.1 C7.1 46.09,57.94 47.31,57.94 47.62,58.26 IC4.14 | C15.+ 65.56,49.37 72.49,56.3 R23.1 | v50.8,36.83 50.59,37.05 C18.1 50.59,38.52 51.44,39.37 IC7.4
  Bottom 0.254: v5.08,62.87 5.08,64.77 4.45,65.41 JP2.1
  Bottom 0.406: v60.01,79.69 60.33,79.38 60.33,73.03 59.37,72.07 v59.37,65.09 | v20.95,63.82 v20.95,73.03 | v56.83,40.32 53.34,36.83 v50.8,36.83 | v18.41,53.34 v18.41,47.31 v18.41,43.18 | v35.56,59.05 30.8,59.05 v29.53,60.33 29.53,68.9 32.38,71.75 v32.38,72.07
ADC_MISO
  Top 0.254: IC4.10 52.7,60.33 51.75,61.28 48.26,61.28 44.45,65.09 36.83,65.09 36.2,65.72 33.66,65.72 32.68,66.69 UC1.16
ADC_MOSI
  Top 0.254: IC4.9 53.98,60.33 52.39,61.91 48.58,61.91 44.77,65.72 37.15,65.72 36.51,66.36 33.97,66.36 33.13,67.19 UC1.17
ADC_SCK
  Top 0.254: IC4.11 51.44,60.01 50.8,60.64 47.94,60.64 47.62,60.96 43.5,60.96 40.01,64.45 36.51,64.45 35.88,65.09 33.34,65.09 32.23,66.19 UC1.15
ADC_SS
  Top 0.254: IC4.8 55.24,60.33 53.02,62.55 48.9,62.55 45.09,66.36 37.47,66.36 36.83,66.99 34.29,66.99 33.59,67.69 UC1.18
AREF
  Top 0.254: IC4.13 48.9,56.83 49.85,55.88 59.37,55.88 | IC5.2 59.37,53.8 59.37,55.88 | 59.37,55.88 60.96,55.88 63.08,58 R23.2 | R23.2 C8.1 | R23.2 72.39,58.31 IC3.1 | R23.2 72.61,58.1
AREF_-10  (via drill 0.6)
  Top 0.254: R38.P$1 68.58,29.23 68.58,30.48 67.31,31.75 55.24,31.75 53.98,30.48 50.48,30.48 v50.16,30.16 | v39.69,34.92 41.27,33.34 44.77,33.34 45.09,33.02 51.75,33.02 v52.07,33.34 52.7,33.97 52.7,35.24 53.02,35.56 R40.1
  Top 0.406: R20.P$1 41.87,54.57 v36.2,48.9 26.04,38.73 23.18,38.73 15.2,30.76 R36.P$1 15.2,24.97 IC8.2 15.24,23.59 C26.1 15.14,22.02 R51.2
  Bottom 0.254: v50.16,30.16 52.07,32.07 v52.07,33.34 | v39.69,34.92 39.69,45.4 v36.2,48.9
AUDIO_OUT  (via drill 0.6)
  Top 0.254: v61.91,53.34 61.28,53.98 60.84,53.98 IC5.4 IC5.3 | v61.91,45.72 61.91,43.81 62.23,43.5 62.23,41.91 58.42,38.1 58.42,35.24 v58.1,34.92 | v58.42,28.26 58.1,28.57 R45.2
  Bottom 0.254: v61.91,45.72 62.23,46.04 62.23,51.75 61.91,52.07 v61.91,53.34 | v58.42,28.26 58.42,34.61 v58.1,34.92
BOOT_FLASH
  Top 0.254: UC1.44 19.57,67.19 17.78,65.41 11.11,65.41 10.32,64.61 5.24,64.61 3.49,62.87 3.49,48.9 3.17,48.58 2.54,48.58 SW3.A 2.44,42.23 | SW3.A' 2.44,42.23 | R33.2 4.45,41.59 3.81,42.23 2.44,42.23
DAC_MOSI
  Top 0.254: IC5.7 59.37,58.6 59.37,59.69 54.61,64.45 49.85,64.45 46.04,68.26 39.37,68.26 38.73,68.9 38.73,71.12 34.92,74.93 29.53,74.93 27.92,73.32 UC1.28
DAC_SCK
  Top 0.254: 60.01,58.59 IC5.6 60.02,57.79 59.85,57.63 57.63,57.63 56.67,58.58 56.67,60.8 53.66,63.82 49.53,63.82 45.72,67.63 39.05,67.63 38.1,68.58 38.1,70.8 34.61,74.3 29.84,74.3 28.92,73.37 UC1.26
DAC_SS
  Top 0.254: IC5.5 60.64,58.58 60.64,57.31 60.33,56.99 57.47,56.99 56.04,58.42 56.04,60.48 53.34,63.18 49.21,63.18 45.4,66.99 38.73,66.99 37.47,68.26 37.47,70.48 34.29,73.66 30.16,73.66 29.42,72.92 UC1.25
DISP_CHAR0
  Top 0.254: R3.1 28.26,104.14 26.99,105.41 5.08,105.41 3.49,103.82 3.49,85.41 1.59,83.5 1.59,66.36 2.86,65.09 9.84,65.09 10.79,66.04 17.46,66.04 19.12,67.69 UC1.43
DISP_CHAR1  (via drill 0.6)
  Top 0.254: R11.1 55.35,103.19 56.2,103.19 56.52,102.87 56.52,99.06 52.7,95.25 49.21,95.25 46.04,92.08 27.62,92.08 26.67,91.12 6.67,91.12 5.4,89.85 5.4,84.45 3.49,82.55 3.49,67.31 3.81,66.99 6.67,66.99 7.3,67.63 v8.89,67.63 | v11.11,64.14 11.75,64.77 18.1,64.77 20.02,66.69 UC1.45
  Bottom 0.254: v8.89,67.63 11.11,65.41 v11.11,64.14
DISP_CHAR2
  Top 0.254: R1.1 11.75,103.82 11.43,104.14 5.71,104.14 4.76,103.19 4.76,84.77 2.86,82.87 2.86,66.99 3.49,66.36 9.21,66.36 10.16,67.31 16.83,67.31 18.21,68.69 UC1.41
DISP_CHAR3
  Top 0.254: R2.1 20,103.82 19.05,104.78 5.4,104.78 4.13,103.5 4.13,85.09 2.22,83.19 2.22,66.67 3.17,65.72 9.53,65.72 10.48,66.67 17.14,66.67 18.66,68.19 UC1.42
DISP_EN  (via drill 0.6)
  Top 0.254: v67.94,79.06 IC2.12 | v67.31,65.09 67.31,65.41 66.04,66.67 61.91,66.67 61.59,66.99 59.05,66.99 58.42,66.36 v56.83,66.36 56.52,66.67 55.24,66.67 53.98,67.94 48.26,67.94 46.67,69.53 41.27,69.53 v40.64,70.17 | v55.24,79.06 IC1.12 | v35.24,68.58 34.92,68.9 32.07,68.9 31.77,69.19 UC1.21
  Bottom 0.254: v67.31,65.09 67.63,65.41 67.63,78.74 v67.94,79.06 | v56.83,66.36 56.83,67.63 57.47,68.26 57.47,76.52 56.83,77.15 55.88,77.15 55.24,77.79 v55.24,79.06 | v40.64,70.17 39.05,70.17 38.73,69.85 37.47,69.85 36.51,68.9 35.56,68.9 v35.24,68.58
DISP_SCK  (via drill 0.6)
  Top 0.254: v69.22,78.11 IC2.11 | v68.58,65.72 68.26,66.04 67.63,66.04 66.36,67.31 62.23,67.31 61.91,67.63 58.1,67.63 | v56.52,78.11 IC1.11 | 58.1,67.63 55.24,67.63 54.29,68.58 48.58,68.58 46.99,70.17 42.55,70.17 v41.91,70.8 | 58.1,67.63 v58.1,67.31 | v36.2,69.85 35.88,69.53 32.38,69.53 32.22,69.69 UC1.22
  Bottom 0.254: v68.58,65.72 68.26,66.04 68.26,77.15 v69.22,78.11 | v58.1,67.31 58.1,77.15 57.15,78.11 v56.52,78.11 | v41.91,70.8 41.59,71.12 39.05,71.12 38.42,70.48 37.15,70.48 36.51,69.85 v36.2,69.85
DISP_SER  (via drill 0.6)
  Top 0.254: v65.41,79.06 IC2.14 | v65.41,65.72 65.09,66.04 61.59,66.04 61.28,66.36 59.37,66.36 58.74,65.72 57.78,65.72 57.47,65.41 56.2,65.41 55.56,66.04 54.93,66.04 53.66,67.31 47.94,67.31 46.35,68.9 40.01,68.9 v39.69,69.22 | v36.51,67.94 36.2,67.63 34.61,67.63 34.04,68.19 UC1.19
  Bottom 0.254: v65.41,65.72 64.77,66.36 64.77,78.42 v65.41,79.06 | v36.51,67.94 37.78,69.22 v39.69,69.22
ENC_A  (via drill 0.6)
  Top 0.254: v24.77,59.69 24.77,60.96 24.92,61.12 UC1.3 | v25.08,88.27 25.72,88.27 26.67,89.22 28.26,89.22 29.21,88.27 35.56,88.27 36.2,87.63 40.32,87.63 40.96,87 42.55,87 43.18,86.36 44.77,86.36 45.4,85.72 46.99,85.72 47.62,85.09 52.07,85.09 52.7,84.45 67.63,84.45 68.54,83.54 SW1.B
  Bottom 0.254: v24.77,59.69 24.77,60.96 25.08,61.28 v25.08,88.27
ENC_B  (via drill 0.6)
  Top 0.254: v25.72,60.64 25.72,61.28 25.42,61.58 UC1.4 | v27.62,88.27 28.26,87.63 35.24,87.63 35.88,87 40.01,87 40.64,86.36 42.23,86.36 42.86,85.72 44.45,85.72 45.09,85.09 46.67,85.09 47.31,84.45 51.75,84.45 52.39,83.82 63.18,83.82 63.5,83.5 63.54,83.5 SW1.A
  Bottom 0.254: v25.72,60.64 25.72,80.33 27.62,82.23 v27.62,88.27
ENC_CLICK  (via drill 0.6)
  Top 0.254: v69.22,84.45 68.58,85.09 53.02,85.09 52.39,85.72 47.94,85.72 47.31,86.36 45.72,86.36 45.09,87 43.5,87 42.86,87.63 41.27,87.63 40.64,88.27 36.51,88.27 35.88,88.9 29.53,88.9 28.57,89.85 24.77,89.85 v22.54,87.63 | v23.81,60.96 24.42,61.57 UC1.2
  Bottom 0.254: v23.81,60.96 24.45,61.59 24.45,80.33 22.54,82.23 v22.54,87.63 | v69.22,84.45 67.94,85.72 67.94,96.5 68.54,97.09 SW1.E
FINE_TUNE
  Top 0.254: UC1.13 31.32,65.19 32.07,64.45 32.07,60.96 33.97,59.05 33.97,53.98 31.11,51.12 23.81,51.12 23.5,50.8 13.97,50.8 12.6,52.17 C31.1 12.7,53.76 R19.P$2
FM_CV
  Top 0.254: IC4.4 51.44,52.39 51.75,52.07 56.52,52.07 57.15,51.44 57.15,45.09 55.24,43.18 IC7.7 55.24,38.63 C17.2 R35.2
GATE
  Top 0.254: R27.1 21.52,49.36 Q6.C 23.81,50.31 23.98,50.48 31.43,50.48 34.61,53.66 34.61,59.37 32.7,61.28 32.7,64.77 31.78,65.69 UC1.14
GND  (via drill 0.6)
  Top 0.254: UC1.20 29.73,68.69 29.61,68.58 29.21,68.58 | 29.24,70.19 UC1.23 | UC1.8 27.42,65.61 | C2.2 23.6,75.88 | UC1.35 24.42,73.66 | v19.68,64.77 20.61,65.69 UC1.47
  other vias: 6.67,100.33 13.65,102.23 21.91,102.23 56.2,97.16 60.64,69.85 71.75,72.39 53.98,78.11 66.67,78.11 62.87,78.74 23.18,59.37 31.11,63.5 26.67,53.66 24.13,53.66 57.63,59.85 52.07,56.83 43.18,59.69 73.03,42.55 68.58,60.64 33.97,72.39 51.44,42.55 51.44,48.9 64.45,24.45 51.75,35.56 27.94,31.43 24.45,17.14 56.52,53.34 59.05,48.58 50.8,65.72 66.04,60.64 27.3,78.74 7.3,86.04 51.75,87 44.77,52.7 39.37,48.9 34.92,43.81 29.84,38.73 36.51,27.3 42.55,21.91 56.2,16.19 40.64,39.69 40.64,37.47 59.69,41.27 60.96,33.66 12.7,62.87 27.3,69.22 5.4,55.88 1.91,55.88 17.78,26.04 11.11,93.34 22.23,75.88 20.64,59.37 47.31,26.67 53.98,21.59 24.45,36.2 19.68,49.85 17.14,49.85 69.53,43.81 39.69,72.71 69.22,12.38 4.45,46.99 31.11,27.3 46.04,40.01 73.34,27.94 25.4,22.86 36.83,39.69 23.18,31.43 28.26,65.72 69.22,72.07 36.83,37.47 6.35,1.27 16.51,1.27 26.67,1.27 36.83,1.27 46.99,1.27 57.15,1.27 67.31,1.27 77.47,1.27 1.27,11.43 1.27,24.13 1.27,34.29 1.27,62.23 1.27,95.25 1.27,105.41 77.47,105.41 67.31,105.41 57.15,105.41 46.99,105.41 29.21,105.41 1.27,85.09 77.47,95.25 77.47,85.09 77.47,74.93 77.47,64.77 77.47,54.61 77.47,44.45 77.47,34.29 11.43,46.99 36.83,19.05 29.21,49.53 44.45,13.97 59.37,17.14 11.75,23.5 75.25,60.64 22.23,78.74 67.63,46.67 60.64,46.67 61.59,54.93 67.31,53.02
  pour Bottom: 0,106.68 0,0 78.74,0 78.74,106.68
  pour Top (isolate 0.203): 0,106.68 0,0 78.74,0 78.74,106.68
JTCK  (via drill 0.6)
  Top 0.254: v8.89,69.22 8.57,69.53 6.67,69.53 6.35,69.22 JP2.4 | v8.89,71.75 18.73,71.75 19.79,70.69 UC1.37
  Bottom 0.254: v8.89,69.22 8.57,69.22 8.57,71.44 v8.89,71.75
JTDI
  Top 0.254: UC1.38 19.34,70.19 18.73,70.8 7.3,70.8 6.35,71.75 JP2.8
JTDO
  Top 0.254: UC1.39 18.89,69.69 18.41,70.17 6.67,70.17 6.35,70.48 JP2.6
JTMS  (via drill 0.6)
  Top 0.254: UC1.34 24.92,71.28 24.45,70.8 23.81,70.8 23.18,71.44 20,71.44 18.73,72.71 v7.62,72.71 | v7.62,68.58 6.99,68.58 6.35,67.94 JP2.2
  Bottom 0.254: v7.62,68.58 7.94,68.9 7.94,72.39 v7.62,72.71
N$1
  Top 0.254: Q3.C 24.13,102.09 24.13,101.28 25.08,100.33 29.21,100.33 30.16,101.28 30.16,104.14 31.43,105.41 35.88,105.41 36.51,104.78 DISP2.16
N$2
  Top 0.254: DISP2.11 49.21,99.06 50.97,100.82 Q4.C
N$3
  Top 0.254: DISP1.16 11.11,99.06 10.48,99.69 9.21,99.69 7.47,101.43 Q1.C
N$4
  Top 0.254: DISP1.11 23.81,99.06 23.18,99.69 17.46,99.69 15.73,101.43 Q2.C
N$5
  Top 0.254: R3.2 28.16,101.28 Q3.B
N$6
  Top 0.254: R11.2 55.15,101.28 Q4.B
N$7
  Top 0.254: UC1.5 25.92,62.03 26.67,61.28 26.67,59.69 24.45,57.47 Q5.2 20.57,56.9 20.64,56.83 20.64,53.76 C9.2
N$8
  Top 0.254: UC1.6 26.42,62.48 27.3,61.59 27.3,59.69 29.53,57.47 Q5.1 30.06,57.3 C10.2
N$9
  Top 0.254: Q1.B 9.77,101.39 R1.2
N$10
  Top 0.254: Q2.B 18.03,101.39 R2.2
N$12  (via drill 0.6)
  Top 0.254: v32.38,34.61 32.38,36.51 34.29,38.42 43.18,38.42 43.5,38.1 44.77,38.1 45.72,37.15 45.72,34.29 46.04,33.97 R41.1 | v32.7,22.54 30.16,22.54 29.84,22.23 IC9.7 29.84,19.27 R53.2
  Bottom 0.254: v32.7,22.54 33.02,22.86 33.02,30.48 32.38,31.11 v32.38,34.61
N$13  (via drill 0.6)
  Top 0.254: R20.P$2 39.37,57.15 39.69,57.47 42.86,57.47 43.5,56.83 43.5,53.66 41.91,52.07 v41.91,48.9 | v41.91,40.64 43.81,38.73 45.09,38.73 46.35,37.47 46.35,35.88 46.67,35.56 R39.1
  Bottom 0.254: v41.91,40.64 v41.91,48.9
N$14  (via drill 0.6)
  Top 0.254: R54.1 30.16,17.36 30.16,14.61 24.77,9.21 v18.73,9.21
  Bottom 0.254: v18.73,9.21 15.88,6.35 J2.P3
N$15  (via drill 0.6)
  Top 0.254: R9.2 45.4,100.97 46.67,99.69 DISP2.12 46.67,97.16 42.86,93.34 21.59,93.34 v21.27,93.03
  Bottom 0.254: v21.27,93.03 DISP1.12
N$16  (via drill 0.6)
  Top 0.254: v26.35,92.39 26.67,92.71 44.13,92.71 47.94,96.52 51.12,96.52 51.75,97.16 DISP2.10 51.75,100.33 52.07,100.65 52.07,103.19 50.16,103.19 49.85,102.87 49.85,101.92 49.31,101.39 R10.2
  Bottom 0.254: v26.35,92.39 DISP1.10
N$17  (via drill 0.6)
  Top 0.254: v26.35,87.31 26.67,87 34.92,87 35.56,86.36 39.69,86.36 40.32,85.72 41.91,85.72 42.55,85.09 44.13,85.09 44.77,84.45 46.35,84.45 46.99,83.82 51.12,83.82 51.75,83.19 DISP2.9 51.75,82.87 R12.2
  Bottom 0.254: DISP1.9 v26.35,87.31
N$18  (via drill 0.6)
  Top 0.254: v21.27,86.68 21.59,86.36 34.61,86.36 35.24,85.72 39.37,85.72 40.01,85.09 41.59,85.09 42.23,84.45 43.81,84.45 44.45,83.82 46.04,83.82 46.67,83.19 DISP2.7 R18.2
  Bottom 0.254: DISP1.7 v21.27,86.68
N$19
  Top 0.254: R13.2 33.97,79.69 33.02,80.64 31.43,80.64 | 31.43,80.64 DISP2.1 | DISP1.1 6.03,81.92 7.3,80.64 31.43,80.64
N$20
  Top 0.254: R4.2 32.7,100.97 31.43,99.69 DISP2.18 31.43,97.16 30.8,96.52 6.67,96.52 6.03,97.16 DISP1.18
N$21  (via drill 0.6)
  Top 0.254: R5.2 35.24,100.97 33.97,99.69 DISP2.17 33.97,97.16 32.7,95.89 8.89,95.89 v8.57,95.57
  Bottom 0.254: v8.57,95.57 DISP1.17
N$22  (via drill 0.6)
  Top 0.254: R6.2 37.78,100.97 39.05,99.69 DISP2.15 39.05,97.16 37.15,95.25 13.97,95.25 v13.65,94.93
  Bottom 0.254: v13.65,94.93 DISP1.15
N$23  (via drill 0.6)
  Top 0.254: R7.2 40.32,100.97 41.59,99.69 DISP2.14 41.59,97.16 39.05,94.61 16.51,94.61 v16.19,94.3
  Bottom 0.254: v16.19,94.3 DISP1.14
N$24  (via drill 0.6)
  Top 0.254: v18.73,86.04 19.05,85.72 34.29,85.72 34.92,85.09 39.05,85.09 39.69,84.45 41.27,84.45 41.91,83.82 43.5,83.82 44.13,83.19 DISP2.6 R17.2
  Bottom 0.254: DISP1.6 v18.73,86.04
N$25  (via drill 0.6)
  Top 0.254: v16.19,85.41 16.51,85.09 33.97,85.09 34.61,84.45 38.73,84.45 39.37,83.82 40.96,83.82 41.59,83.19 DISP2.5 R16.2
  Bottom 0.254: DISP1.5 v16.19,85.41
N$26  (via drill 0.6)
  Top 0.254: v13.65,84.77 13.97,84.45 33.66,84.45 34.29,83.82 38.42,83.82 39.05,83.19 DISP2.4 R15.2
  Bottom 0.254: DISP1.4 v13.65,84.77
N$27
  Top 0.254: DISP1.2 8.57,83.19 9.21,83.82 33.34,83.82 33.97,83.19 DISP2.2 33.97,81.28 34.92,80.33 35.88,80.33 36.51,79.69 R14.2
N$28  (via drill 0.6)
  Top 0.254: R8.2 42.86,100.97 44.13,99.69 DISP2.13 44.13,97.16 40.96,93.98 19.05,93.98 v18.73,93.66
  Bottom 0.254: v18.73,93.66 DISP1.13
N$29
  Top 0.254: IC7.2 48.9,38.63 C16.1 R34.1 R39.2 R41.2
N$30  (via drill 0.6)
  Top 0.254: IC2.7 70.48,72.71 72.71,74.93 72.71,84.45 70.17,87 56.83,87 53.66,90.17 40.64,90.17 v40.32,89.85 | v40.32,99.69 39.05,100.97 39.05,102.55 38.52,103.08 R6.1
  Bottom 0.254: v40.32,89.85 v40.32,99.69
N$31  (via drill 0.6)
  Top 0.254: IC1.14 52.7,79.38 53.34,80.01 57.15,80.01 v58.74,78.42 | v59.05,73.66 59.37,73.98 70.8,73.98 71.75,74.93 IC2.9
  Bottom 0.254: v58.74,78.42 59.05,78.11 v59.05,73.66
N$32  (via drill 0.6)
  Top 0.254: IC2.15 64.14,79.38 64.77,80.01 69.85,80.01 70.8,80.96 70.8,85.41 69.85,86.36 56.52,86.36 53.98,88.9 49.53,88.9 v49.21,89.22 | v47.94,99.69 46.99,100.65 46.99,102.23 46.14,103.08 R9.1
  Bottom 0.254: v49.21,89.22 49.21,92.71 47.94,93.98 v47.94,99.69
N$33  (via drill 0.6)
  Top 0.254: IC2.1 62.87,68.58 66.99,68.58 68.26,67.31 73.34,67.31 74.61,68.58 74.61,90.81 72.07,93.34 58.1,93.34 v57.47,92.71 | v58.1,94.93 58.1,102.87 56.2,104.78 49.85,104.78 48.9,103.82 R10.1
  Bottom 0.254: v57.47,92.71 58.1,93.34 v58.1,94.93
N$34  (via drill 0.6)
  Top 0.254: v61.28,82.87 R12.1 | IC2.2 64.14,71.12 63.82,71.44 61.91,71.44 v61.59,71.12
  Bottom 0.254: v61.59,71.12 61.28,71.44 v61.28,82.87
N$35  (via drill 0.6)
  Top 0.254: IC2.3 65.41,71.12 64.45,72.07 54.29,72.07 53.02,73.34 49.85,73.34 48.9,74.3 47.31,74.3 v46.35,75.25 | v47.94,80.64 47.94,77.79 47.41,77.25 R18.1
  Bottom 0.254: v46.35,75.25 46.35,79.06 v47.94,80.64
N$36
  Top 0.254: IC2.4 66.67,71.12 65.09,72.71 54.93,72.71 53.66,73.98 50.16,73.98 49.21,74.93 48.26,74.93 46.99,76.2 34.29,76.2 33.97,76.52 R13.1
N$37  (via drill 0.6)
  Top 0.254: IC2.5 67.94,68.58 68.58,67.94 73.03,67.94 73.98,68.9 73.98,90.49 71.75,92.71 59.05,92.71 57.78,91.44 33.02,91.44 v32.7,91.12 | R4.1 32.8,103.19 33.34,103.19 33.97,102.55 33.97,100.97 v32.7,99.69
  Bottom 0.254: v32.7,91.12 v32.7,99.69
N$38  (via drill 0.6)
  Top 0.254: IC2.6 69.22,68.58 72.39,68.58 73.34,69.53 73.34,84.77 70.48,87.63 57.15,87.63 53.98,90.81 35.56,90.81 v35.24,90.49 | R5.1 35.24,103.82 34.92,104.14 v33.97,104.14
  Bottom 0.254: v35.24,90.49 35.24,102.87 v33.97,104.14
N$39  (via drill 0.6)
  Top 0.254: IC1.15 51.44,79.38 52.7,80.64 69.53,80.64 70.17,81.28 70.17,85.09 69.53,85.72 56.2,85.72 53.66,88.27 45.09,88.27 43.81,89.53 43.18,89.53 v42.86,89.22 | v42.86,99.69 41.59,100.97 41.59,102.55 41.06,103.08 R7.1
  Bottom 0.254: v42.86,89.22 v42.86,99.69
N$40  (via drill 0.6)
  Top 0.254: IC1.1 50.16,70.48 49.85,70.8 48.58,70.8 47.62,71.75 44.77,71.75 v44.45,72.07 | v45.4,80.64 45.4,77.79 44.87,77.25 R17.1
  Bottom 0.254: v44.45,72.07 45.4,73.03 v45.4,80.64
N$41  (via drill 0.6)
  Top 0.254: IC1.2 51.44,71.12 51.12,71.44 48.9,71.44 47.94,72.39 45.72,72.39 44.45,73.66 v42.86,73.66 | v42.86,80.64 42.86,77.79 42.33,77.25 R16.1
  Bottom 0.254: v42.86,73.66 v42.86,80.64
N$42  (via drill 0.6)
  Top 0.254: IC1.3 52.7,71.12 51.75,72.07 49.21,72.07 48.26,73.03 46.04,73.03 44.13,74.93 40.64,74.93 v40.32,74.61 | v40.32,80.64 40.32,77.79 39.79,77.25 R15.1
  Bottom 0.254: v40.32,74.61 v40.32,80.64
N$43  (via drill 0.6)
  Top 0.254: IC1.4 53.98,71.12 52.39,72.71 49.53,72.71 48.58,73.66 46.35,73.66 44.45,75.56 38.1,75.56 v37.78,75.25 | v37.78,80.64 37.78,77.79 37.25,77.25 R14.1
  Bottom 0.254: v37.78,75.25 v37.78,80.64
N$44  (via drill 0.6)
  Top 0.254: IC1.5 55.24,68.58 55.56,68.26 62.23,68.26 62.55,67.94 66.67,67.94 67.94,66.67 73.66,66.67 75.25,68.26 75.25,91.12 72.39,93.98 49.53,93.98 v47.94,92.39 | v45.4,99.69 44.13,100.97 44.13,102.55 43.6,103.08 R8.1
  Bottom 0.254: v47.94,92.39 45.4,94.93 v45.4,99.69
N$45
  Top 0.254: R54.2 R53.1 28.57,19.27 IC9.6
N$46  (via drill 0.6)
  Top 0.254: v34.61,21.91 34.61,16.51 27.3,9.21 J3.P3 | v34.29,32.38 34.61,32.7 36.83,32.7 37.47,32.07 44.13,32.07 44.45,31.75 53.34,31.75 54.61,33.02 58.74,33.02 59.69,33.97 59.69,37.47 63.82,41.59 v63.82,42.86 | v63.82,52.39 64.24,52.81 R24.1
  Bottom 0.254: v63.82,52.39 63.5,52.07 63.5,45.4 63.82,45.09 v63.82,42.86 | v34.61,21.91 35.24,22.54 35.24,24.77 34.29,25.72 v34.29,32.38
N$47
  Top 0.254: R48.1 39.37,20.88 39.65,20.6 39.69,20.56 39.69,8.26 40.01,7.94 J4.P3
N$48
  Top 0.254: R24.2 66.04,54.08 R21.P$2
N$49
  Top 0.406: 74.14,34.13 74.14,33.81 | IC6.2 75.94,40.06 73.98,38.1 73.98,34.75 C19.+ 74.14,34.13 | R49.1 67.63,24.77 71.12,28.26 71.12,31.11 74.14,34.13
N$50
  Top 0.254: R37.P$1 41.87,28.54 38.42,25.08 33.66,25.08 33.34,24.77 28.26,24.77 27.94,25.08 24.45,25.08 23.5,26.04 IC9.13 23.5,29 R43.1
N$51
  Top 0.254: R30.1 38.42,45.4 27.3,34.29 24.45,34.29 22.01,31.85 R43.2 22.23,29 IC9.14
N$52  (via drill 0.6)
  Top 0.254: v65.09,41.91 63.82,40.64 63.82,34.92 61.28,32.38 54.93,32.38 53.66,31.11 44.13,31.11 43.81,31.43 36.83,31.43 36.2,32.07 35.88,32.07 v35.56,31.75 | v36.2,23.18 33.66,23.18 33.34,23.5 27.62,23.5 27.3,23.81 24.77,23.81 23.5,22.54 IC9.2 23.5,19.27 R52.1
  Bottom 0.254: v65.09,41.91 65.09,43.18 64.45,43.81 64.45,45.4 64.14,45.72 64.14,51.44 66.99,54.29 67.94,54.29 68.58,54.93 68.54,54.97 R21.P$1 | v35.56,31.75 34.92,31.11 34.92,26.04 35.88,25.08 35.88,23.5 v36.2,23.18
N$53  (via drill 0.6)
  Top 0.254: v33.34,33.66 34.29,33.66 34.61,33.34 37.47,33.34 38.1,32.7 44.45,32.7 44.77,32.38 53.02,32.38 53.76,33.12 R42.1 | R52.2 22.23,19.27 IC9.1 22.23,22.86 23.81,24.45 27.62,24.45 27.94,24.13 v34.29,24.13
  Bottom 0.254: v34.29,24.13 33.66,24.77 33.66,30.8 33.34,31.11 v33.34,33.66
N$55  (via drill 0.6)
  Top 0.254: v62.87,44.45 62.87,41.59 59.05,37.78 59.05,34.29 58.74,33.97 R42.2 R40.2 55.35,35.56 R35.1 C17.1 53.98,38.63 IC7.6
  Bottom 0.254: v62.87,44.45 62.87,53.34 63.54,54.02 R21.P$3
N$56
  Top 0.406: JP1.1 JP1.2 D1.A
N$57
  Top 0.254: J1.P3 1.91,10.16 7.62,15.88 7.62,31.75 10.79,34.92 10.79,38.73 18.1,46.04 R29.1
N$58
  Top 0.254: R31.1 40.01,43.5 39.37,42.86 36.83,42.86 30.06,36.09 R44.2 29.84,29 29.84,28.57 IC9.8
N$59  (via drill 0.6)
  Top 0.254: v38.1,43.81 39.05,43.81 39.69,44.45 45.72,44.45 45.94,44.66 R30.2 | R30.2 R28.2 | R30.2 46.67,45.4 46.99,45.09 48.58,45.09 48.9,45.4 IC7.13 48.9,48.36 C13.1 R25.1
  Bottom 0.254: v38.1,43.81 38.1,32.07 36.87,30.84 R37.P$3
N$60  (via drill 0.6)
  Top 0.254: v40.32,24.77 40.32,10.79 42.23,8.89 50.16,8.89 52.35,6.71 J5.P3 | v38.42,26.35 38.1,26.04 R47.1
  Bottom 0.254: v38.42,26.35 38.73,26.35 v40.32,24.77
N$61  (via drill 0.6)
  Top 0.254: R28.1 36.51,46.99 26.99,37.47 24.13,37.47 v17.78,31.11
  Bottom 0.254: v17.78,31.11 13.34,31.11 12.7,30.48 R36.P$2
N$62
  Top 0.254: R37.P$2 39.37,30.48 39.69,30.8 43.18,30.8 43.5,30.48 43.5,28.26 42.55,27.3 41.59,27.3 39.37,25.08 R48.2
N$63
  Top 0.254: R47.2 32.7,26.04 32.07,25.4 29.21,25.4 28.57,26.04 IC9.9 28.57,28.57 28.57,29 R44.1
N$64
  Top 0.406: JP1.9 JP1.10 71.12,14.29 71.11,14.29 D2.C
N$65  (via drill 0.6)
  Top 0.254: R38.P$2 66.04,30.48 65.72,30.8 55.24,30.8 54.29,29.84 51.75,29.84 50.48,28.57 46.99,28.57 v46.04,29.53 | R32.1 44.13,41.81 v44.13,39.69
  Bottom 0.254: v44.13,39.69 46.04,37.78 v46.04,29.53
N$66
  Top 0.254: Q6.B 22.86,46.36 22.54,46.04 R29.2
N$67
  Top 0.254: IC10.6 IC10.7 C21.2 51.02,26.77 49.85,27.94 45.72,27.94 44.45,26.67 C24.+
N$68
  Top 0.254: R50.2 47.2,19.47 45.41,21.26 C24.-
N$69
  Top 0.254: R46.1 55.24,26.77 C22.1 55.35,25.5 54.93,25.08 54.87,25.08 IC10.5
N$70
  Top 0.254: R32.2 R31.2 46.67,43.5 47.62,44.45 48.9,44.45 49.53,45.09 53.98,45.09 IC7.9 53.98,48.36 C14.1 R26.1
N$71
  Top 0.254: R45.1 55.24,28.47 R46.2 C21.1
N$72  (via drill 0.6)
  Top 0.254: 53.98,13.97 55.88,12.06 59.37,12.06 v62.55,8.89 | 53.98,13.97 R56.1 | R55.1 50.8,14.29 51.12,13.97 53.98,13.97 | v66.67,8.89 75.56,8.89 76.83,7.62 J6.P3
  Bottom 0.254: v62.55,8.89 v66.67,8.89
N$73
  Top 0.254: IC10.1 R55.2 50.8,16.93 C29.2
N$75
  Top 0.254: 48.9,21.27 R50.1 51.85,21.17 52.07,20.95 IC10.2 52.07,18.1 52.39,17.78 C29.1 R56.2
PARAM1_CV
  Top 0.254: IC4.1 47.73,53.49 47.62,53.39 47.62,51.75 47.41,51.54 R25.2 C13.2 47.62,48.36 IC7.14
PARAM2_CV
  Top 0.254: 55.14,46.67 IC7.8 55.24,48.36 C14.2 R26.2 | IC4.2 48.9,52.39 50.48,50.8 55.24,50.8 55.46,50.59 R26.2 | R26.2 55.46,49.63
PITCH_CV
  Top 0.254: IC4.3 50.16,52.39 51.12,51.44 55.88,51.44 56.52,50.8 56.52,45.4 55.56,44.45 49.85,44.45 47.62,42.23 IC7.1 47.62,38.63 C16.2 R34.2
RESET  (via drill 0.6)
  Top 0.254: UC1.7 26.92,62.93 27.94,61.91 27.94,60.33 28.89,59.37 32.7,59.37 33.34,58.74 33.34,54.29 30.8,51.75 v20,51.75 | v22.86,72.39 22.54,72.07 20.32,72.07 18.73,73.66 7.3,73.66 6.67,73.03 JP2.10 | 6.54,52.07 SW2.B' SW2.B 6.35,59.06 6.35,59.69 6.25,59.79 R22.1 v5.08,58.42
  Bottom 0.254: v22.86,72.39 23.81,71.44 23.81,62.55 21.91,60.64 21.91,53.66 v20,51.75 | v5.08,58.42 5.08,59.69 6.03,60.64 6.03,65.72 6.67,66.36 6.67,72.39 6.03,73.03 JP2.10
RX
  Top 0.254: JP3.4 10.16,78.11 10.79,78.74 19.37,78.74 20.95,77.15 24.77,77.15 26.42,75.5 UC1.31
TX
  Top 0.254: JP3.5 7.62,78.74 8.26,79.38 19.68,79.38 21.27,77.79 25.08,77.79 26.92,75.95 UC1.30
VCC  (via drill 0.6)
  Top 0.254: C28.1 26.04,18.52
  Top 0.406: IC10.8 50.76,24.87 C23.1 48.9,23.5 49.53,22.86 57.47,22.86 57.78,22.54 C25.+ 59.51,21.77 60.64,20.64 | C28.1 26.14,18.73 26.04,18.84 IC9.4 26.04,20 | C28.1 26.04,18.73 | v27.3,14.61 27.3,18.1 26.77,18.63 C28.1 | v29.21,8.89 29.21,5.74 30.98,3.97 63.34,3.97 64.45,5.08 64.45,9.84 62.23,12.06 62.23,17.46 60.64,19.05 60.64,20.64 | 60.64,20.64 67.63,20.64 | 67.63,20.64 D1.C | 67.63,20.64 R49.2
  Bottom 0.406: v29.21,8.89 29.21,12.7 v27.3,14.61
VEE  (via drill 0.6)
  Top 0.406: v62.23,19.37 63.5,18.1 63.5,14.92 | 63.5,14.92 63.5,12.38 65.25,10.64 65.25,4.6 63.82,3.17 18.26,3.17 16.73,4.71 R51.1 16.83,22.01 16.83,23.18 v20.32,26.67 | v59.05,19.37 58.74,19.37 58.52,19.58 C27.2 56.16,19.62 IC10.4 | 63.5,14.92 63.99,14.92 C30.- 64.77,15.7 64.77,16.51 66.35,18.09 D2.A | v25.08,31.43 25.4,31.11 25.4,29.84 25.61,29.63 C20.2 26.35,28.57 26.04,28.26 IC9.11
  Bottom 0.406: v62.23,19.37 v59.05,19.37 | v20.32,26.67 v25.08,31.43

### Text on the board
tNames: Braids | cc-by-sa Olivier Gillet, 2015. v5 | RESET | SYSBOOT
bNames: Braids | cc-by-sa Olivier Gillet, 2015. v5 | TX | RX | GND | +12V | GND | GND | GND | -12V | Red stripe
